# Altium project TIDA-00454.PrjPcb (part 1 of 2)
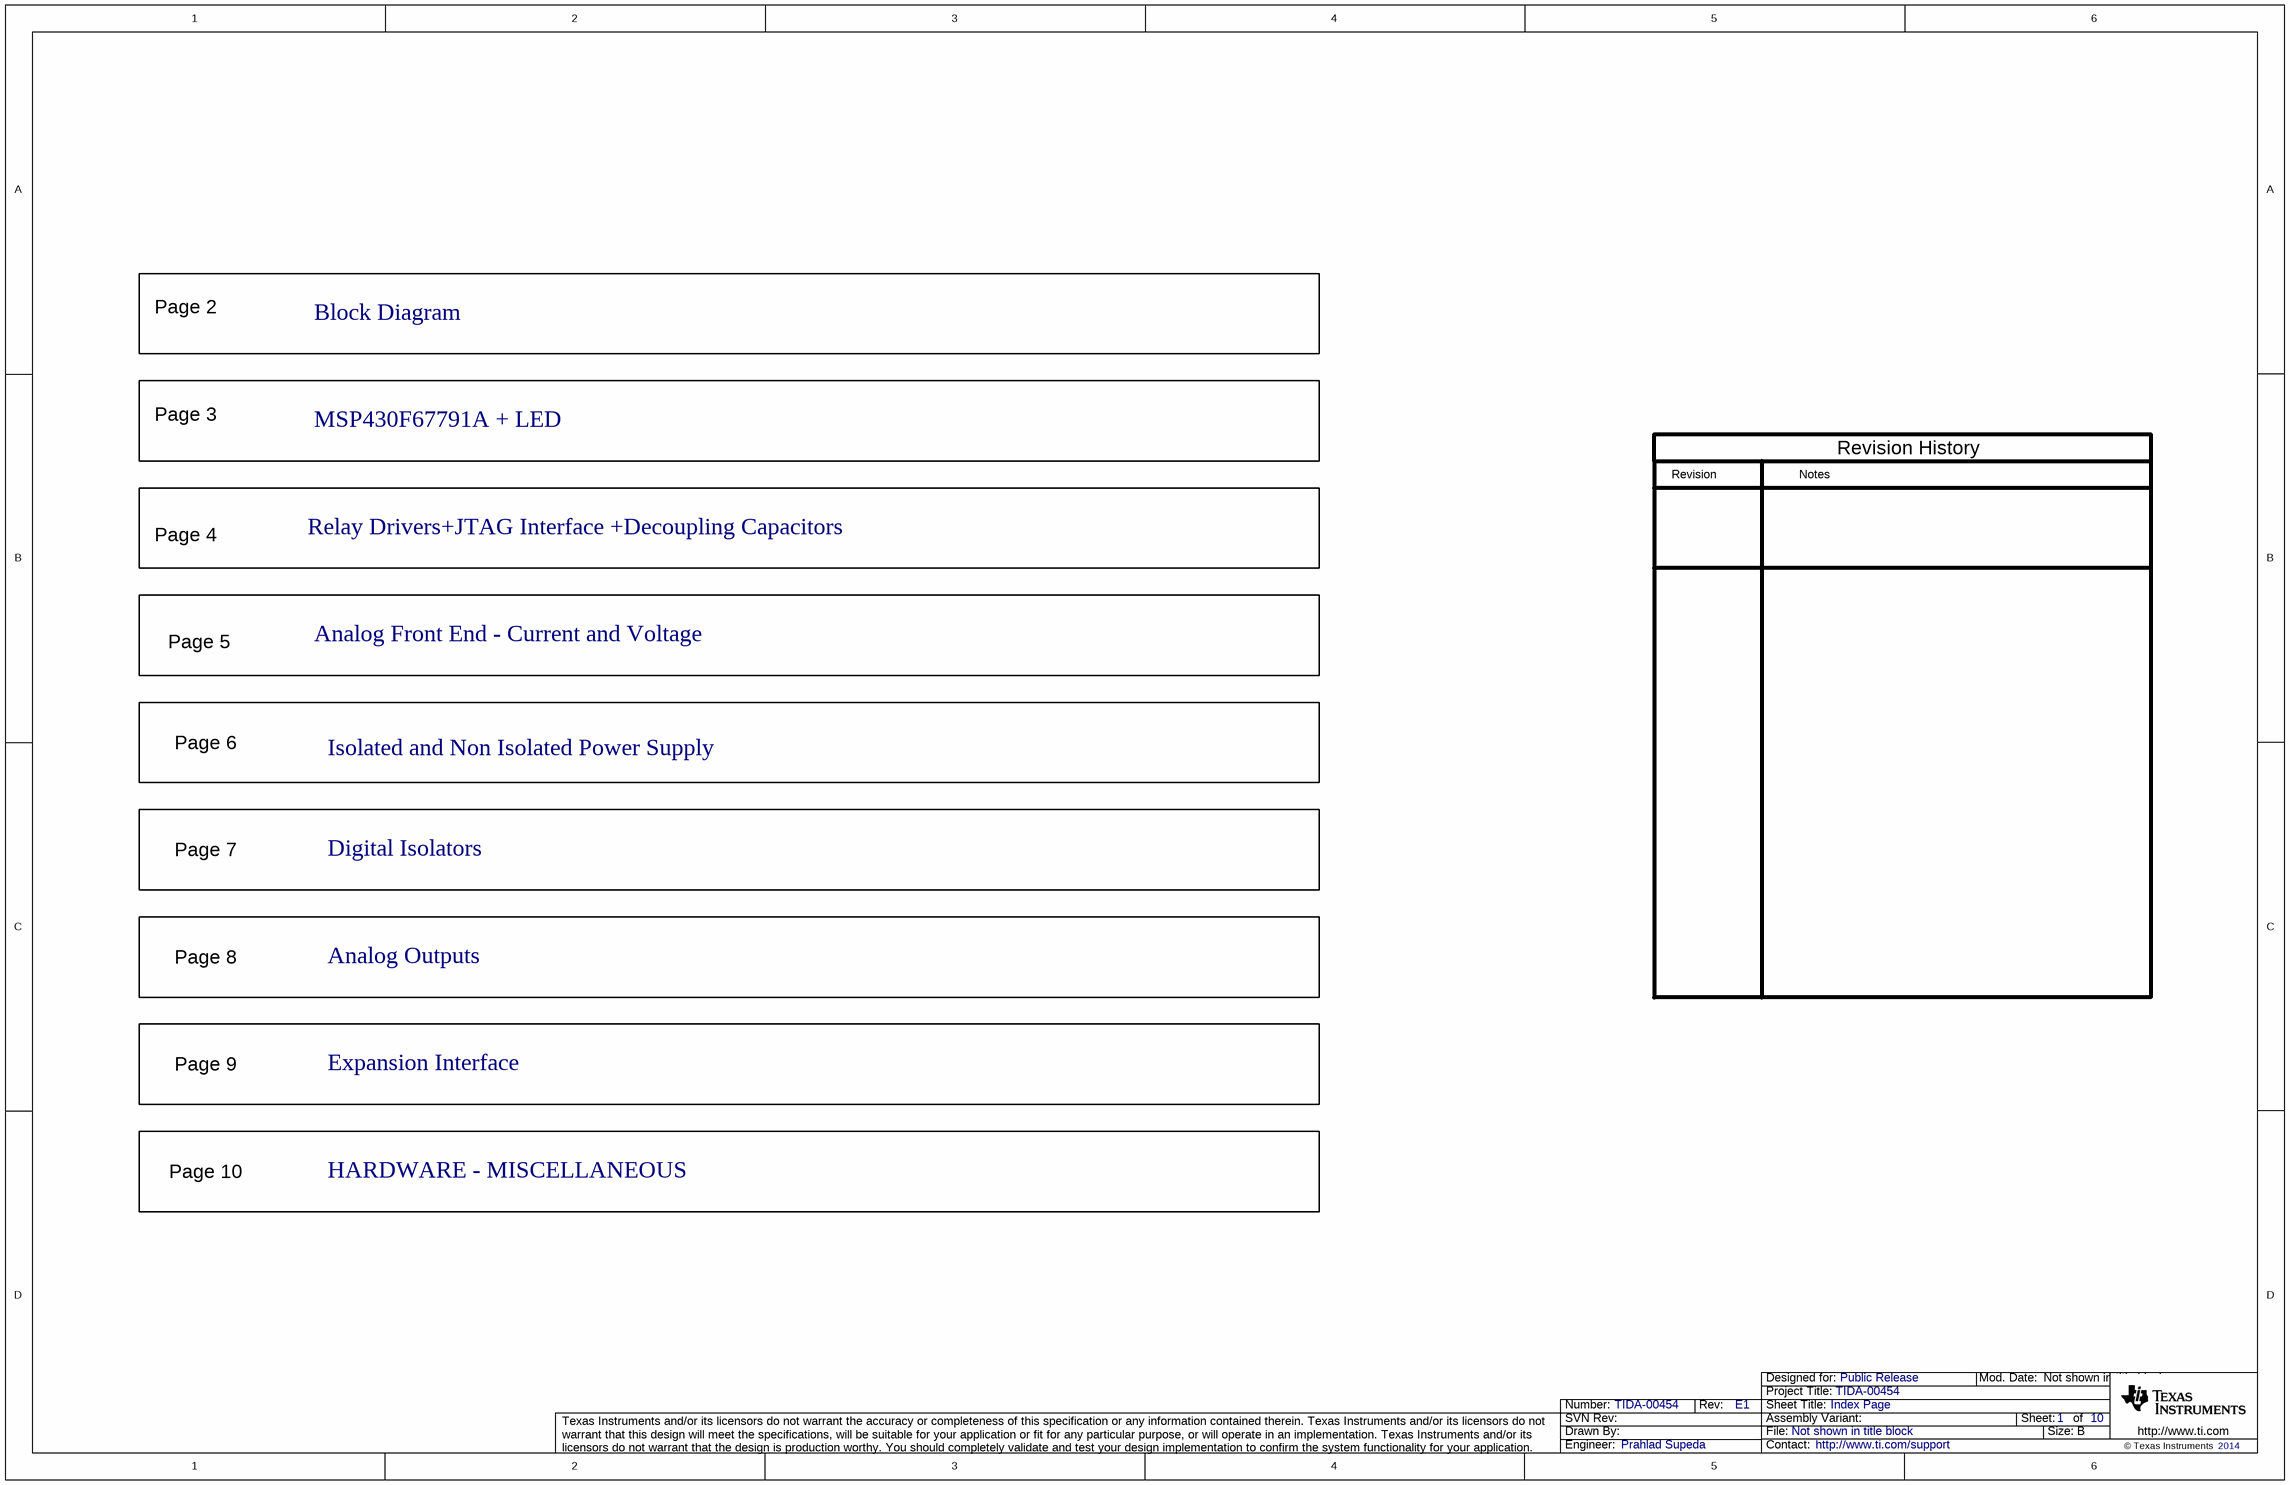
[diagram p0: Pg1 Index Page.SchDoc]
CopyrightYear: 2014; PCB_Rev: E1; PRJ_Customer: Public Release; PRJ_Engineer: Prahlad Supeda; PRJ_Number: TIDA-00454; PRJ_Title: TIDA-00454; SCH_Rev: E1; TechSupport: http://www.ti.com/support
10 sheets, 327 parts. Net scope: flat (ports and power ports of the same name join across sheets).
Board file: TIDA-00454.PcbDoc
Sheets:
  Pg1 Index Page.SchDoc
  Pg2 Block Diagram.SchDoc
  Pg3.MSP430F67791A+LED.SchDoc
  Pg4. Relay Drivers+JTAG Interface +Decoupling Capacitors.SchDoc
  Pg5.Analog Front End - Current and Voltage.SchDoc
  Pg6.Isolated and Non Isolated Power Supply.SchDoc
  Pg7.Digital Isolators.SchDoc
  Pg8. Analog Outputs.SchDoc
  Pg9 Expansion Interface.SchDoc
  Pg10.HARDWARE - MISCELLANEOUS..SchDoc

## Sheet Pg1 Index Page.SchDoc: Index Page
size 431 x 279 mm; Date: Not shown in title block; ApprovedBy: Not shown in title block; CheckedBy: Not shown in title block; Author: Not shown in title block; CompanyName: Not shown in title block; Engineer: Not shown in title block; Organization: Not shown in title block; Address1: Not shown in title block; Address2: Not shown in title block; Address3: Not shown in title block; Address4: Not shown in title block; DocumentNumber: 1; Revision: Use project parameter SCH_Rev; SheetNumber: 1; SheetTotal: 10; PageSetup: Record=PageOptions¦CenterHorizontal=True¦CenterVertical=True¦PrintScale=1.00¦XCorrection=1.00¦YCorrection=1.00¦PrintKind=0¦BorderSize=5000000¦LeftOffset=0¦BottomOffset=0¦Orientation=2¦PaperLength=1000¦PaperWidth=1000¦Scale=100¦PaperSource=15¦PrintQuality=600¦MediaType=1¦DitherType=10¦PaperKind=Letter¦PrintScaleMode=1

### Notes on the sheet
- Page 2
- Block Diagram
- Page 3
- MSP430F67791A + LED
- Revision
- Notes
- Revision History
- Page 4
- Relay Drivers+JTAG Interface +Decoupling Capacitors
- Page 5
- Analog Front End - Current and Voltage
- Page 6
- Isolated and Non Isolated Power Supply
- Page 7
- Digital Isolators
- Page 8
- Analog Outputs
- Page 9
- Expansion Interface
- Page 10
- HARDWARE - MISCELLANEOUS

## Sheet Pg2 Block Diagram.SchDoc: Block Diagram
size 431 x 279 mm; Date: Not shown in title block; ApprovedBy: Not shown in title block; CheckedBy: Not shown in title block; Author: Not shown in title block; CompanyName: Not shown in title block; Engineer: Not shown in title block; Organization: Not shown in title block; Address1: Not shown in title block; Address2: Not shown in title block; Address3: Not shown in title block; Address4: Not shown in title block; DocumentNumber: 2; Revision: Use project parameter SCH_Rev; SheetNumber: 2; SheetTotal: 10; PageSetup: Record=PageOptions|CenterHorizontal=True|CenterVertical=True|PrintScale=1.00|XCorrection=1.00|YCorrection=1.00|PrintKind=0|BorderSize=5000000|LeftOffset=0|BottomOffset=0|Orientation=2|PaperLength=1000|PaperWidth=1000|Scale=100|PaperSource=15|PrintQuality=600|MediaType=1|DitherType=10|PaperKind=Letter|PrintScaleMode=1

## Sheet Pg3.MSP430F67791A+LED.SchDoc: MSP430F6779 + Crystal
size 431 x 279 mm; Date: Not shown in title block; ApprovedBy: Not shown in title block; CheckedBy: Not shown in title block; Author: Not shown in title block; CompanyName: Not shown in title block; Engineer: Not shown in title block; Organization: Not shown in title block; Address1: Not shown in title block; Address2: Not shown in title block; Address3: Not shown in title block; Address4: Not shown in title block; DocumentNumber: 6; Revision: Use project parameter SCH_Rev; SheetNumber: 3; SheetTotal: 10; PageSetup: Record=PageOptions¦CenterHorizontal=True¦CenterVertical=True¦PrintScale=1.00¦XCorrection=1.00¦YCorrection=1.00¦PrintKind=0¦BorderSize=5000000¦LeftOffset=0¦BottomOffset=0¦Orientation=2¦PaperLength=1000¦PaperWidth=1000¦Scale=100¦PaperSource=15¦PrintQuality=600¦MediaType=1¦DitherType=10¦PaperKind=Letter¦PrintScaleMode=1
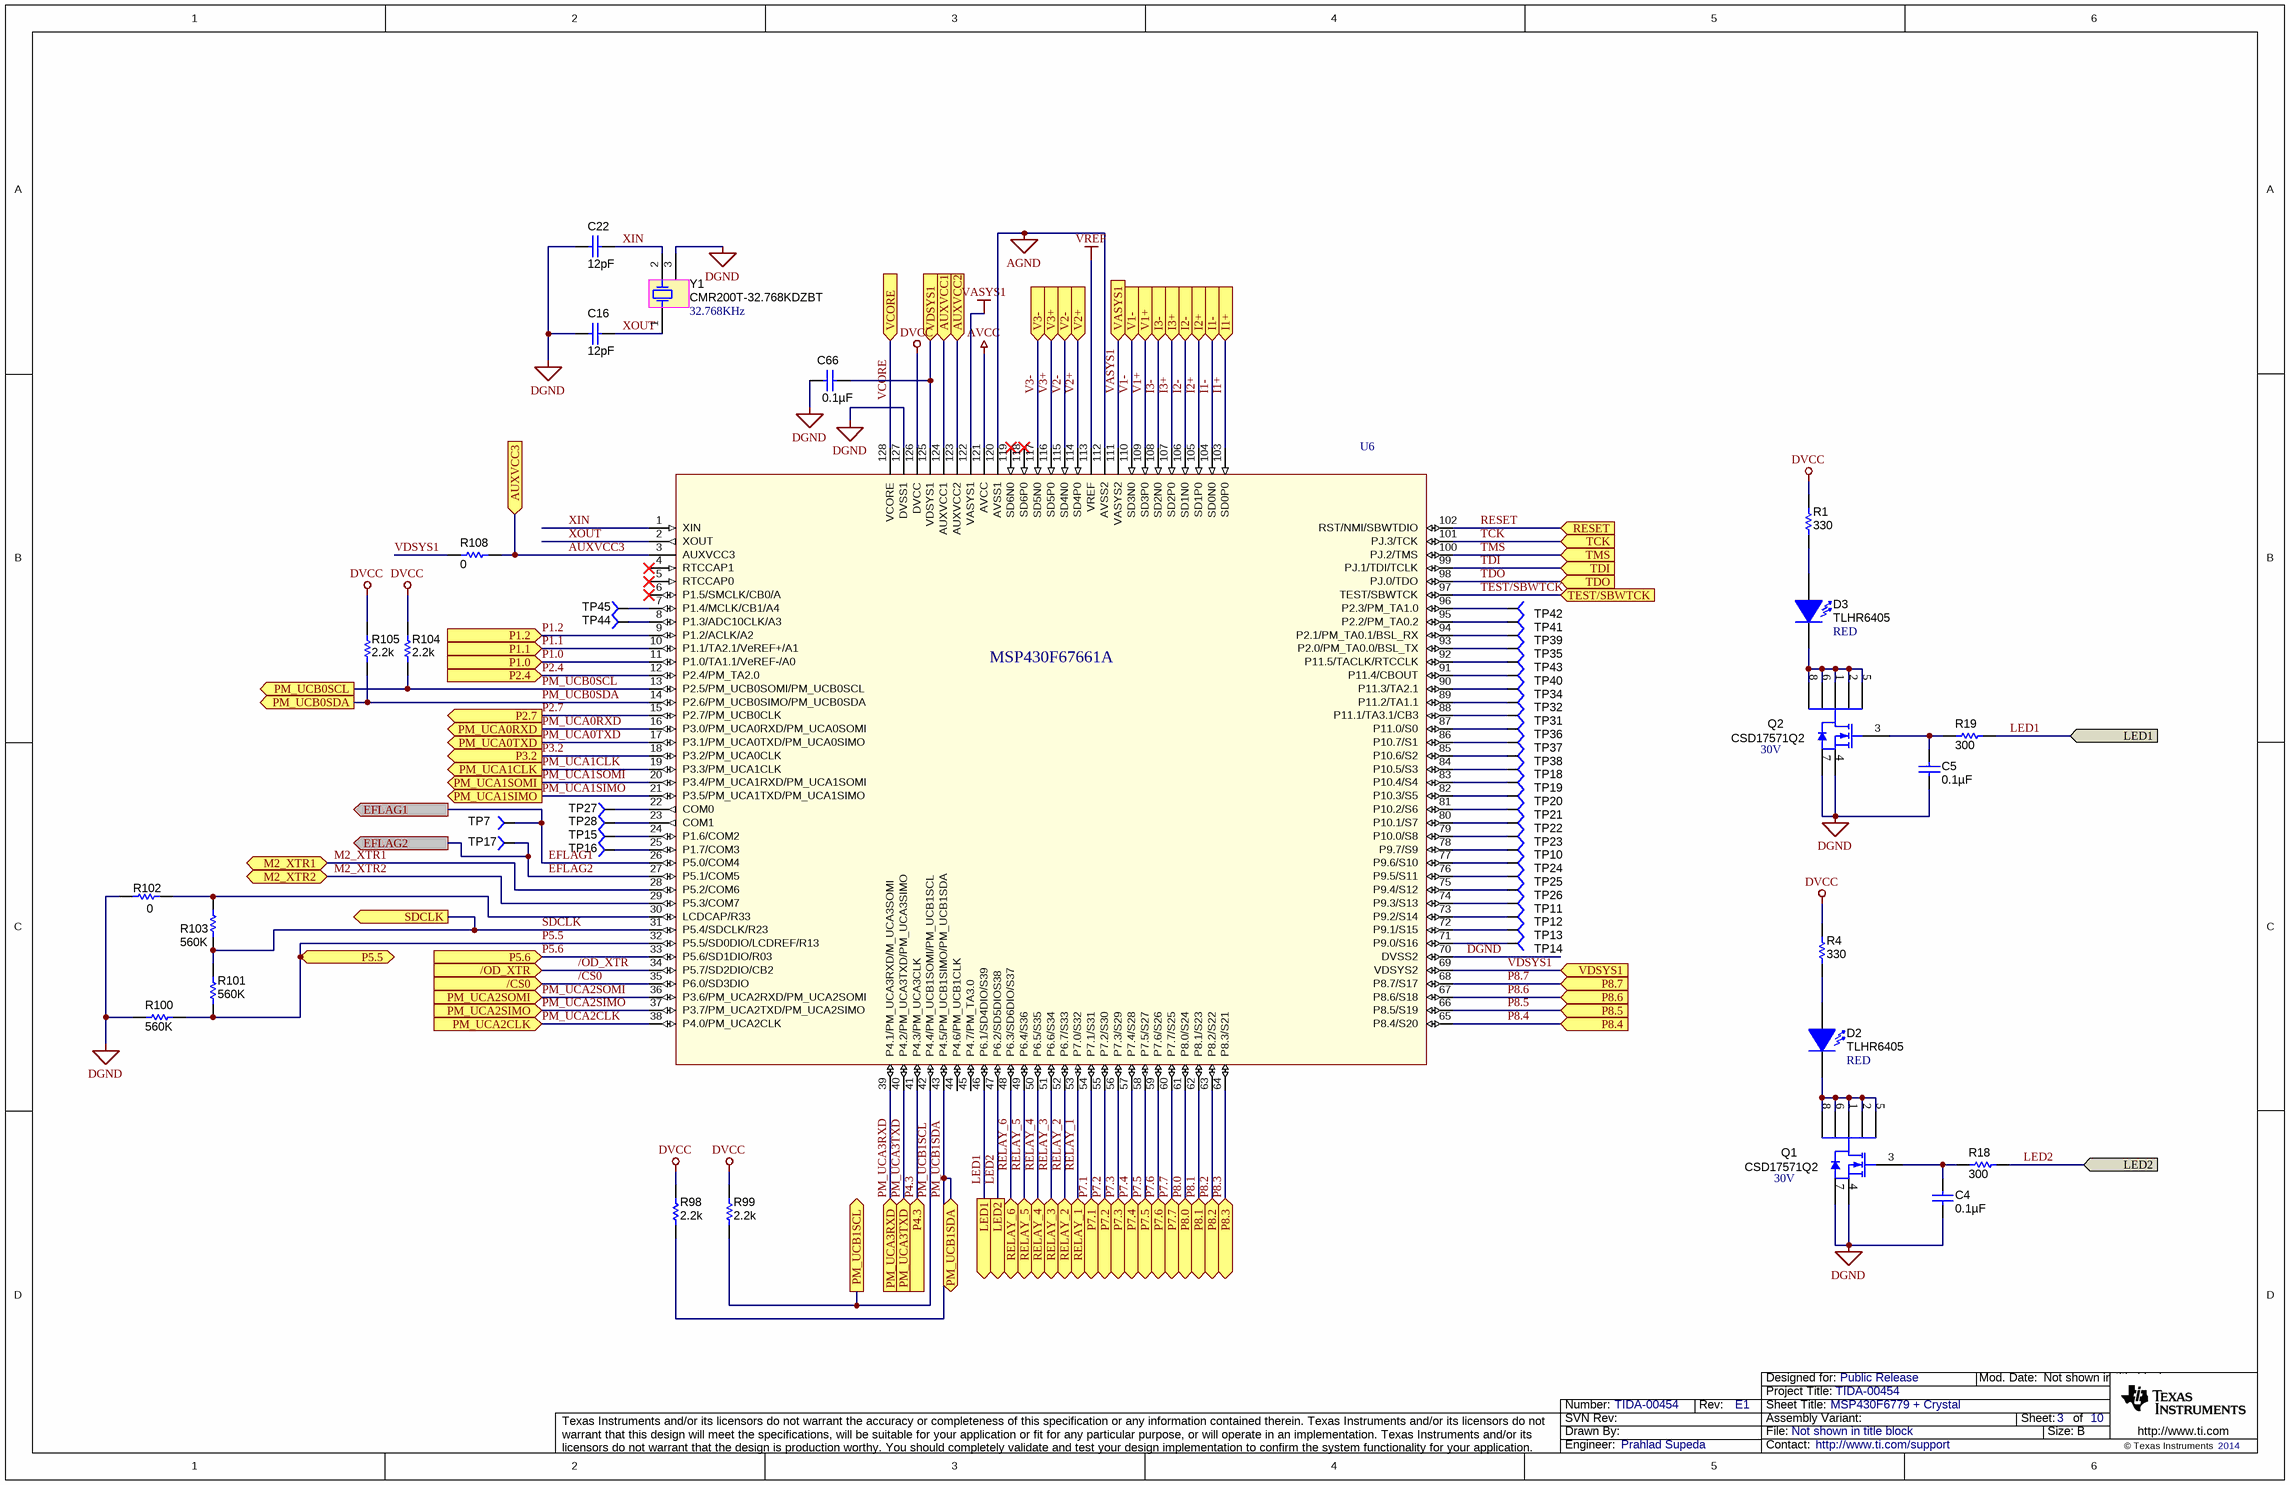
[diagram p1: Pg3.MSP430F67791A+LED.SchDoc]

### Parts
C4  ValueDisplayed: 0.1µF  [0603]  (hidden comment: 06033C104JAT2A)
C5  ValueDisplayed: 0.1µF  [0603]  (hidden comment: 06033C104JAT2A)
C16  ValueDisplayed: 12pF  [0603]  (hidden comment: 06035A120JAT2A)
C22  ValueDisplayed: 12pF  [0603]  (hidden comment: 06035A120JAT2A)
C66  ValueDisplayed: 0.1µF  [0603]  (hidden comment: 06033C104JAT2A)
D2  TLHR6405  value RED  [LED_5MM]
D3  TLHR6405  value RED  [LED_5MM]
Q1  CSD17571Q2  value 30V  [SON_CSD17571Q2]
Q2  CSD17571Q2  value 30V  [SON_CSD17571Q2]
R1  value 330  [0603]  (hidden comment: CRCW0603330RJNEA)
R4  value 330  [0603]  (hidden comment: CRCW0603330RJNEA)
R18  value 300  [0603]  (hidden comment: CRCW0603300RJNEA)
R19  value 300  [0603]  (hidden comment: CRCW0603300RJNEA)
R98  value 2.2k  [0603]  (hidden comment: CRCW06032K20JNEA)
R99  value 2.2k  [0603]  (hidden comment: CRCW06032K20JNEA)
R100  value 560K  [0603]  (hidden comment: CRCW0603560KFKEA)
R101  value 560K  [0603]  (hidden comment: CRCW0603560KFKEA)
R102  value 0  [0603]  (hidden comment: CRCW06030000Z0EA)
R103  value 560K  [0603]  (hidden comment: CRCW0603560KFKEA)
R104  value 2.2k  [0603]  (hidden comment: CRCW06032K20JNEA)
R105  value 2.2k  [0603]  (hidden comment: CRCW06032K20JNEA)
R108  value 0  [0805_HV]  (hidden comment: CRCW08050000Z0EA)
TP7  TP-040_RND  [TP_25MIL-SMT]  (value not drawn)
TP10  TP-040_RND  [TP_25MIL-SMT]  (value not drawn)
TP11  TP-040_RND  [TP_25MIL-SMT]  (value not drawn)
TP12  TP-040_RND  [TP_25MIL-SMT]  (value not drawn)
TP13  TP-040_RND  [TP_25MIL-SMT]  (value not drawn)
TP14  TP-040_RND  [TP_25MIL-SMT]  (value not drawn)
TP15  TP-040_RND  [TP_25MIL-SMT]  (value not drawn)
TP16  TP-040_RND  [TP_25MIL-SMT]  (value not drawn)
TP17  TP-040_RND  [TP_25MIL-SMT]  (value not drawn)
TP18  TP-040_RND  [TP_25MIL-SMT]  (value not drawn)
TP19  TP-040_RND  [TP_25MIL-SMT]  (value not drawn)
TP20  TP-040_RND  [TP_25MIL-SMT]  (value not drawn)
TP21  TP-040_RND  [TP_25MIL-SMT]  (value not drawn)
TP22  TP-040_RND  [TP_25MIL-SMT]  (value not drawn)
TP23  TP-040_RND  [TP_25MIL-SMT]  (value not drawn)
TP24  TP-040_RND  [TP_25MIL-SMT]  (value not drawn)
TP25  TP-040_RND  [TP_25MIL-SMT]  (value not drawn)
TP26  TP-040_RND  [TP_25MIL-SMT]  (value not drawn)
TP27  TP-040_RND  [TP_25MIL-SMT]  (value not drawn)
TP28  TP-040_RND  [TP_25MIL-SMT]  (value not drawn)
TP31  TP-040_RND  [TP_25MIL-SMT]  (value not drawn)
TP32  TP-040_RND  [TP_25MIL-SMT]  (value not drawn)
TP34  TP-040_RND  [TP_25MIL-SMT]  (value not drawn)
TP35  TP-040_RND  [TP_25MIL-SMT]  (value not drawn)
TP36  TP-040_RND  [TP_25MIL-SMT]  (value not drawn)
TP37  TP-040_RND  [TP_25MIL-SMT]  (value not drawn)
TP38  TP-040_RND  [TP_25MIL-SMT]  (value not drawn)
TP39  TP-040_RND  [TP_25MIL-SMT]  (value not drawn)
TP40  TP-040_RND  [TP_25MIL-SMT]  (value not drawn)
TP41  TP-040_RND  [TP_25MIL-SMT]  (value not drawn)
TP42  TP-040_RND  [TP_25MIL-SMT]  (value not drawn)
TP43  TP-040_RND  [TP_25MIL-SMT]  (value not drawn)
TP44  TP-040_RND  [TP_25MIL-SMT]  (value not drawn)
TP45  TP-040_RND  [TP_25MIL-SMT]  (value not drawn)
U6  MSP430F67661A  [QFP50P1600X2200X160-128N]
Y1  CMR200T-32.768KDZBT  Frequency: 32.768KHz  [XTAL_CMR200T]

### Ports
/CS0 (in), /OD_XTR (in), AUXVCC1 (in), AUXVCC2 (in), AUXVCC3 (in), EFLAG1 (out), EFLAG2 (out), I1+ (in), I1- (in), I2+ (in), I2- (in), I3+ (in), I3- (in), LED1 (in), LED1 (out), LED2 (in), LED2 (out), M2_XTR1, M2_XTR2, P1.0 (in), P1.1 (in), P1.2 (in), P2.4 (in), P2.7 (out), P3.2 (out), P4.3 (in), P5.5 (in), P5.6 (in), P7.1, P7.2, P7.3, P7.4, P7.5, P7.6, P7.7, P8.0, P8.1, P8.2, P8.3, P8.4 (in), P8.5 (in), P8.6 (in), P8.7 (in), PM_UCA0RXD (out), PM_UCA0TXD (out), PM_UCA1CLK (out), PM_UCA1SIMO (out), PM_UCA1SOMI (out), PM_UCA2CLK (in), PM_UCA2SIMO (in), PM_UCA2SOMI (in), PM_UCA3RXD (in), PM_UCA3TXD (in), PM_UCB0SCL (out), PM_UCB0SDA (out), PM_UCB1SCL (out), PM_UCB1SDA (bidir), RELAY_1, RELAY_2, RELAY_3, RELAY_4, RELAY_5, RELAY_6, RESET (in), SDCLK (out), TCK (in), TDI (in), TDO (in), TEST/SBWTCK (in), TMS (in), V1+ (in), V1- (in), V2+ (in), V2- (in), V3+ (in), V3- (in), VASYS1 (in), VCORE (in), VDSYS1 (in)

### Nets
AGND: U6.112(AVSS2) U6.120(AVSS1)
AVCC: U6.121(AVCC)
DGND: C4.2 C5.2 C16.2 C22.2 C66.1 Q1.4(S) Q1.7(S) Q2.4(S) Q2.7(S) R100.2 R102.1 U6.70(DVSS2) U6.127(DVSS1) Y1.3
DVCC: R1.2 R4.2 R98.2 R99.2 R104.2 R105.2 U6.126(DVCC)
VASYS1: U6.111(VASYS2) U6.122(VASYS1) ; port VASYS1
VREF: U6.113(VREF)
/CS0: U6.35(P6.0/SD3DIO) ; port /CS0
/OD_XTR: U6.34(P5.7/SD2DIO/CB2) ; port /OD_XTR
AUXVCC1: U6.124(AUXVCC1) ; port AUXVCC1
AUXVCC2: U6.123(AUXVCC2) ; port AUXVCC2
AUXVCC3: R108.2 U6.3(AUXVCC3) ; port AUXVCC3
EFLAG1: TP7.1 U6.26(P5.0/COM4) ; port EFLAG1
EFLAG2: TP17.1 U6.27(P5.1/COM5) ; port EFLAG2
I1+: U6.103(SD0P0) ; port I1+
I1-: U6.104(SD0N0) ; port I1-
I2+: U6.105(SD1P0) ; port I2+
I2-: U6.106(SD1N0) ; port I2-
I3+: U6.107(SD2P0) ; port I3+
I3-: U6.108(SD2N0) ; port I3-
LED1: R19.1 U6.46(P6.1/SD4DIO/S39) ; port LED1
LED2: R18.1 U6.47(P6.2/SD5DIOS38) ; port LED2
M2_XTR1: U6.28(P5.2/COM6) ; port M2_XTR1
M2_XTR2: U6.29(P5.3/COM7) ; port M2_XTR2
P1.0: U6.11(P1.0/TA1.1/VeREF-/A0) ; port P1.0
P1.1: U6.10(P1.1/TA2.1/VeREF+/A1) ; port P1.1
P1.2: U6.9(P1.2/ACLK/A2) ; port P1.2
P2.4: U6.12(P2.4/PM_TA2.0) ; port P2.4
P2.7: U6.15(P2.7/PM_UCB0CLK) ; port P2.7
P3.2: U6.18(P3.2/PM_UCA0CLK) ; port P3.2
P4.3: U6.41(P4.3/PM_UCA3CLK) ; port P4.3
P5.5: R100.1 R101.1 U6.32(P5.5/SD0DIO/LCDREF/R13) ; port P5.5
P5.6: U6.33(P5.6/SD1DIO/R03) ; port P5.6
P7.1: U6.54(P7.1/S31) ; port P7.1
P7.2: U6.55(P7.2/S30) ; port P7.2
P7.3: U6.56(P7.3/S29) ; port P7.3
P7.4: U6.57(P7.4/S28) ; port P7.4
P7.5: U6.58(P7.5/S27) ; port P7.5
P7.6: U6.59(P7.6/S26) ; port P7.6
P7.7: U6.60(P7.7/S25) ; port P7.7
P8.0: U6.61(P8.0/S24) ; port P8.0
P8.1: U6.62(P8.1/S23) ; port P8.1
P8.2: U6.63(P8.2/S22) ; port P8.2
P8.3: U6.64(P8.3/S21) ; port P8.3
P8.4: U6.65(P8.4/S20) ; port P8.4
P8.5: U6.66(P8.5/S19) ; port P8.5
P8.6: U6.67(P8.6/S18) ; port P8.6
P8.7: U6.68(P8.7/S17) ; port P8.7
PM_UCA0RXD: U6.16(P3.0/PM_UCA0RXD/PM_UCA0SOMI) ; port PM_UCA0RXD
PM_UCA0TXD: U6.17(P3.1/PM_UCA0TXD/PM_UCA0SIMO) ; port PM_UCA0TXD
PM_UCA1CLK: U6.19(P3.3/PM_UCA1CLK) ; port PM_UCA1CLK
PM_UCA1SIMO: U6.21(P3.5/PM_UCA1TXD/PM_UCA1SIMO) ; port PM_UCA1SIMO
PM_UCA1SOMI: U6.20(P3.4/PM_UCA1RXD/PM_UCA1SOMI) ; port PM_UCA1SOMI
PM_UCA2CLK: U6.38(P4.0/PM_UCA2CLK) ; port PM_UCA2CLK
PM_UCA2SIMO: U6.37(P3.7/PM_UCA2TXD/PM_UCA2SIMO) ; port PM_UCA2SIMO
PM_UCA2SOMI: U6.36(P3.6/PM_UCA2RXD/PM_UCA2SOMI) ; port PM_UCA2SOMI
PM_UCA3RXD: U6.39(P4.1/PM_UCA3RXD/M_UCA3SOMI) ; port PM_UCA3RXD
PM_UCA3TXD: U6.40(P4.2/PM_UCA3TXD/PM_UCA3SIMO) ; port PM_UCA3TXD
PM_UCB0SCL: R104.1 U6.13(P2.5/PM_UCB0SOMI/PM_UCB0SCL) ; port PM_UCB0SCL
PM_UCB0SDA: R105.1 U6.14(P2.6/PM_UCB0SIMO/PM_UCB0SDA) ; port PM_UCB0SDA
PM_UCB1SCL: R99.1 U6.42(P4.4/PM_UCB1SOMI/PM_UCB1SCL) ; port PM_UCB1SCL
PM_UCB1SDA: R98.1 U6.43(P4.5/PM_UCB1SIMO/PM_UCB1SDA) ; port PM_UCB1SDA
RELAY_1: U6.53(P7.0/S32) ; port RELAY_1
RELAY_2: U6.52(P6.7/S33) ; port RELAY_2
RELAY_3: U6.51(P6.6/S34) ; port RELAY_3
RELAY_4: U6.50(P6.5/S35) ; port RELAY_4
RELAY_5: U6.49(P6.4/S36) ; port RELAY_5
RELAY_6: U6.48(P6.3/SD6DIO/S37) ; port RELAY_6
RESET: U6.102(RST/NMI/SBWTDIO) ; port RESET
SDCLK: R101.2 R103.1 U6.31(P5.4/SDCLK/R23) ; port SDCLK
TCK: U6.101(PJ.3/TCK) ; port TCK
TDI: U6.99(PJ.1/TDI/TCLK) ; port TDI
TDO: U6.98(PJ.0/TDO) ; port TDO
TEST/SBWTCK: U6.97(TEST/SBWTCK) ; port TEST/SBWTCK
TMS: U6.100(PJ.2/TMS) ; port TMS
V1+: U6.109(SD3P0) ; port V1+
V1-: U6.110(SD3N0) ; port V1-
V2+: U6.114(SD4P0) ; port V2+
V2-: U6.115(SD4N0) ; port V2-
V3+: U6.116(SD5P0) ; port V3+
V3-: U6.117(SD5N0) ; port V3-
VCORE: U6.128(VCORE) ; port VCORE
VDSYS1: C66.2 R108.1 U6.69(VDSYS2) U6.125(VDSYS1) ; port VDSYS1
XIN: C22.1 U6.1(XIN) Y1.2
XOUT: C16.1 U6.2(XOUT) Y1.1
NetC4_1: C4.1 Q1.3(G) R18.2
NetC5_1: C5.1 Q2.3(G) R19.2
NetD2_1: D2.1(K) Q1.1(D) Q1.2(D) Q1.5(D) Q1.6(D) Q1.8(D)
NetD2_2: D2.2(A) R4.1
NetD3_1: D3.1(K) Q2.1(D) Q2.2(D) Q2.5(D) Q2.6(D) Q2.8(D)
NetD3_2: D3.2(A) R1.1
NetR102_2: R102.2 R103.2 U6.30(LCDCAP/R33)
NetTP10_1: TP10.1 U6.78(P9.7/S9)
NetTP11_1: TP11.1 U6.74(P9.3/S13)
NetTP12_1: TP12.1 U6.73(P9.2/S14)
NetTP13_1: TP13.1 U6.72(P9.1/S15)
NetTP14_1: TP14.1 U6.71(P9.0/S16)
NetTP15_1: TP15.1 U6.24(P1.6/COM2)
NetTP16_1: TP16.1 U6.25(P1.7/COM3)
NetTP18_1: TP18.1 U6.84(P10.5/S3)
NetTP19_1: TP19.1 U6.83(P10.4/S4)
NetTP20_1: TP20.1 U6.82(P10.3/S5)
NetTP21_1: TP21.1 U6.81(P10.2/S6)
NetTP22_1: TP22.1 U6.80(P10.1/S7)
NetTP23_1: TP23.1 U6.79(P10.0/S8)
NetTP24_1: TP24.1 U6.77(P9.6/S10)
NetTP25_1: TP25.1 U6.76(P9.5/S11)
NetTP26_1: TP26.1 U6.75(P9.4/S12)
NetTP27_1: TP27.1 U6.22(COM0)
NetTP28_1: TP28.1 U6.23(COM1)
NetTP31_1: TP31.1 U6.88(P11.1/TA3.1/CB3)
NetTP32_1: TP32.1 U6.89(P11.2/TA1.1)
NetTP34_1: TP34.1 U6.90(P11.3/TA2.1)
NetTP35_1: TP35.1 U6.93(P2.0/PM_TA0.0/BSL_TX)
NetTP36_1: TP36.1 U6.87(P11.0/S0)
NetTP37_1: TP37.1 U6.86(P10.7/S1)
NetTP38_1: TP38.1 U6.85(P10.6/S2)
NetTP39_1: TP39.1 U6.94(P2.1/PM_TA0.1/BSL_RX)
NetTP40_1: TP40.1 U6.91(P11.4/CBOUT)
NetTP41_1: TP41.1 U6.95(P2.2/PM_TA0.2)
NetTP42_1: TP42.1 U6.96(P2.3/PM_TA1.0)
NetTP43_1: TP43.1 U6.92(P11.5/TACLK/RTCCLK)
NetTP44_1: TP44.1 U6.8(P1.3/ADC10CLK/A3)
NetTP45_1: TP45.1 U6.7(P1.4/MCLK/CB1/A4)

Not connected (* = marked no-connect by the designer): U6 4(RTCCAP1)* 5(RTCCAP0)* 6(P1.5/SMCLK/CB0/A)* 44(P4.6/PM_UCB1CLK) 45(P4.7/PM_TA3.0) 118(SD6P0)* 119(SD6N0)*

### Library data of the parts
C4 C5 C66 = 06033C104JAT2A: CAP, CERM, 0.1uF, 25V, +/-5%, X7R, 0603; Manufacturer: AVX; Polarized: N; CompType: Capacitor; U/M: EA; Cap_F: 0.0000001; Tolerance_%: 5; ESR_Ohm: 0.05; Value1: 0.05 ohm; VDC_V: 25; TaMin_C: -55; TaMax_C: 125
C16 C22 = 06035A120JAT2A: CAP, CERM, 12pF, 50V, +/-5%, C0G/NP0, 0603; Manufacturer: AVX; Polarized: N; CompType: Capacitor; U/M: EA; Cap_F: 0.000000000012; Tolerance_%: 5; ESR_Ohm: 0.363; Value1: 0.363 ohm; VDC_V: 50; TaMin_C: -55; TaMax_C: 125
D2 D3 = TLHR6405: LED, 5MM, RED, TH; Manufacturer: VISHAY; SymbolCreator: x0199378
Q1 Q2 = CSD17571Q2: MOSFET, N-CH, 30V, 22A, SON 2X2 MM; Manufacturer: TEXAS INSTRUMENTS; CompType: POWER MOSFET
R1 R4 = CRCW0603330RJNEA: RES, 330 ohm, 5%, 0.1W, 0603; Manufacturer: Vishay-Dale; CompType: Resistor; Value_Code: 330R; Tolerance_%: 5; Power_W: 0.1; VDC_V: 75; TempCo: 200 ppm/C; EIA_Code: E24; U/M: EA
R18 R19 = CRCW0603300RJNEA: RES, 300 ohm, 5%, 0.1W, 0603; Manufacturer: Vishay-Dale; CompType: Resistor; Value_Code: 300R; Tolerance_%: 5; Power_W: 0.1; VDC_V: 75; TempCo: 200 ppm/C; EIA_Code: E24; U/M: EA
R98 R99 R104 R105 = CRCW06032K20JNEA: RES, 2.2k ohm, 5%, 0.1W, 0603; Manufacturer: Vishay-Dale; CompType: Resistor; Res_ohm: 2200; Value_Code: 2k20; Tolerance_%: 5; Power_W: 0.1; VDC_V: 75; TempCo: 200 ppm/C; EIA_Code: E24; U/M: EA
R100 R101 R103 = CRCW06032K20JNEA: RES 560K OHM 1/10W 1% 0603 SMD; Manufacturer: Vishay-Dale; CompType: Resistor; Tolerance_%: 1; Power_W: 0.1; Value2: 0.1W; VDC_V: 75; TempCo: 100 ppm/C; EIA_Code: E24; U/M: EA
R102 = CRCW08050000Z0EA: RES 0.0 OHM 1/10W JUMP 0603 SMD; Manufacturer: Vishay-Dale; CompType: Resistor; Value_Code: 0000; Tolerance_%: 5; Power_W: 0.125; Value2: 0.1W; VDC_V: 150; EIA_Code: E24; U/M: EA
R108 = CRCW0805330KJNEA: RES, 0 ohm, 5%, 0.125W, 0805; Manufacturer: Vishay-Dale; CompType: Resistor; Tolerance_%: 5; Power_W: 0.125; VDC_V: 150; TempCo: 200 ppm/C; EIA_Code: E24; U/M: EA
TP7 TP10-TP28 TP35-TP38 TP44 TP45 = TP-040_RND: Test Point, SMT 25mil; Manufacturer: STD; Value: STD
TP31 TP32 TP34 TP39-TP43 = TP-040_RND: Test Point, O.040 Hole; Manufacturer: STD; Value: STD
U6 = MSP430F6779IPEU: IC, MCU 16BIT 512KB FLASH, LQFP-128; Manufacturer: TEXAS INSTRUMENTS; SymbolCreator: x0199378
Y1 = CMR200T-32.768KDZBT: CRYSTAL, 32.768KHz, 6PF, +/- 20PPM, SMD-3P; Manufacturer: CITIZEN; SymbolCreator: x0199378

## Sheet Pg4. Relay Drivers+JTAG Interface +Decoupling Capacitors.SchDoc: JTAG Interface + LEDs + Decoupling Capacitors
size 431 x 279 mm; Date: Not shown in title block; ApprovedBy: Not shown in title block; CheckedBy: Not shown in title block; Author: Not shown in title block; CompanyName: Not shown in title block; Engineer: Not shown in title block; Organization: Not shown in title block; Address1: Not shown in title block; Address2: Not shown in title block; Address3: Not shown in title block; Address4: Not shown in title block; DocumentNumber: 5; Revision: Use project parameter SCH_Rev; SheetNumber: 4; SheetTotal: 10; PageSetup: Record=PageOptions¦CenterHorizontal=True¦CenterVertical=True¦PrintScale=1.00¦XCorrection=1.00¦YCorrection=1.00¦PrintKind=0¦BorderSize=5000000¦LeftOffset=0¦BottomOffset=0¦Orientation=2¦PaperLength=1000¦PaperWidth=1000¦Scale=100¦PaperSource=15¦PrintQuality=600¦MediaType=1¦DitherType=10¦PaperKind=Letter¦PrintScaleMode=1
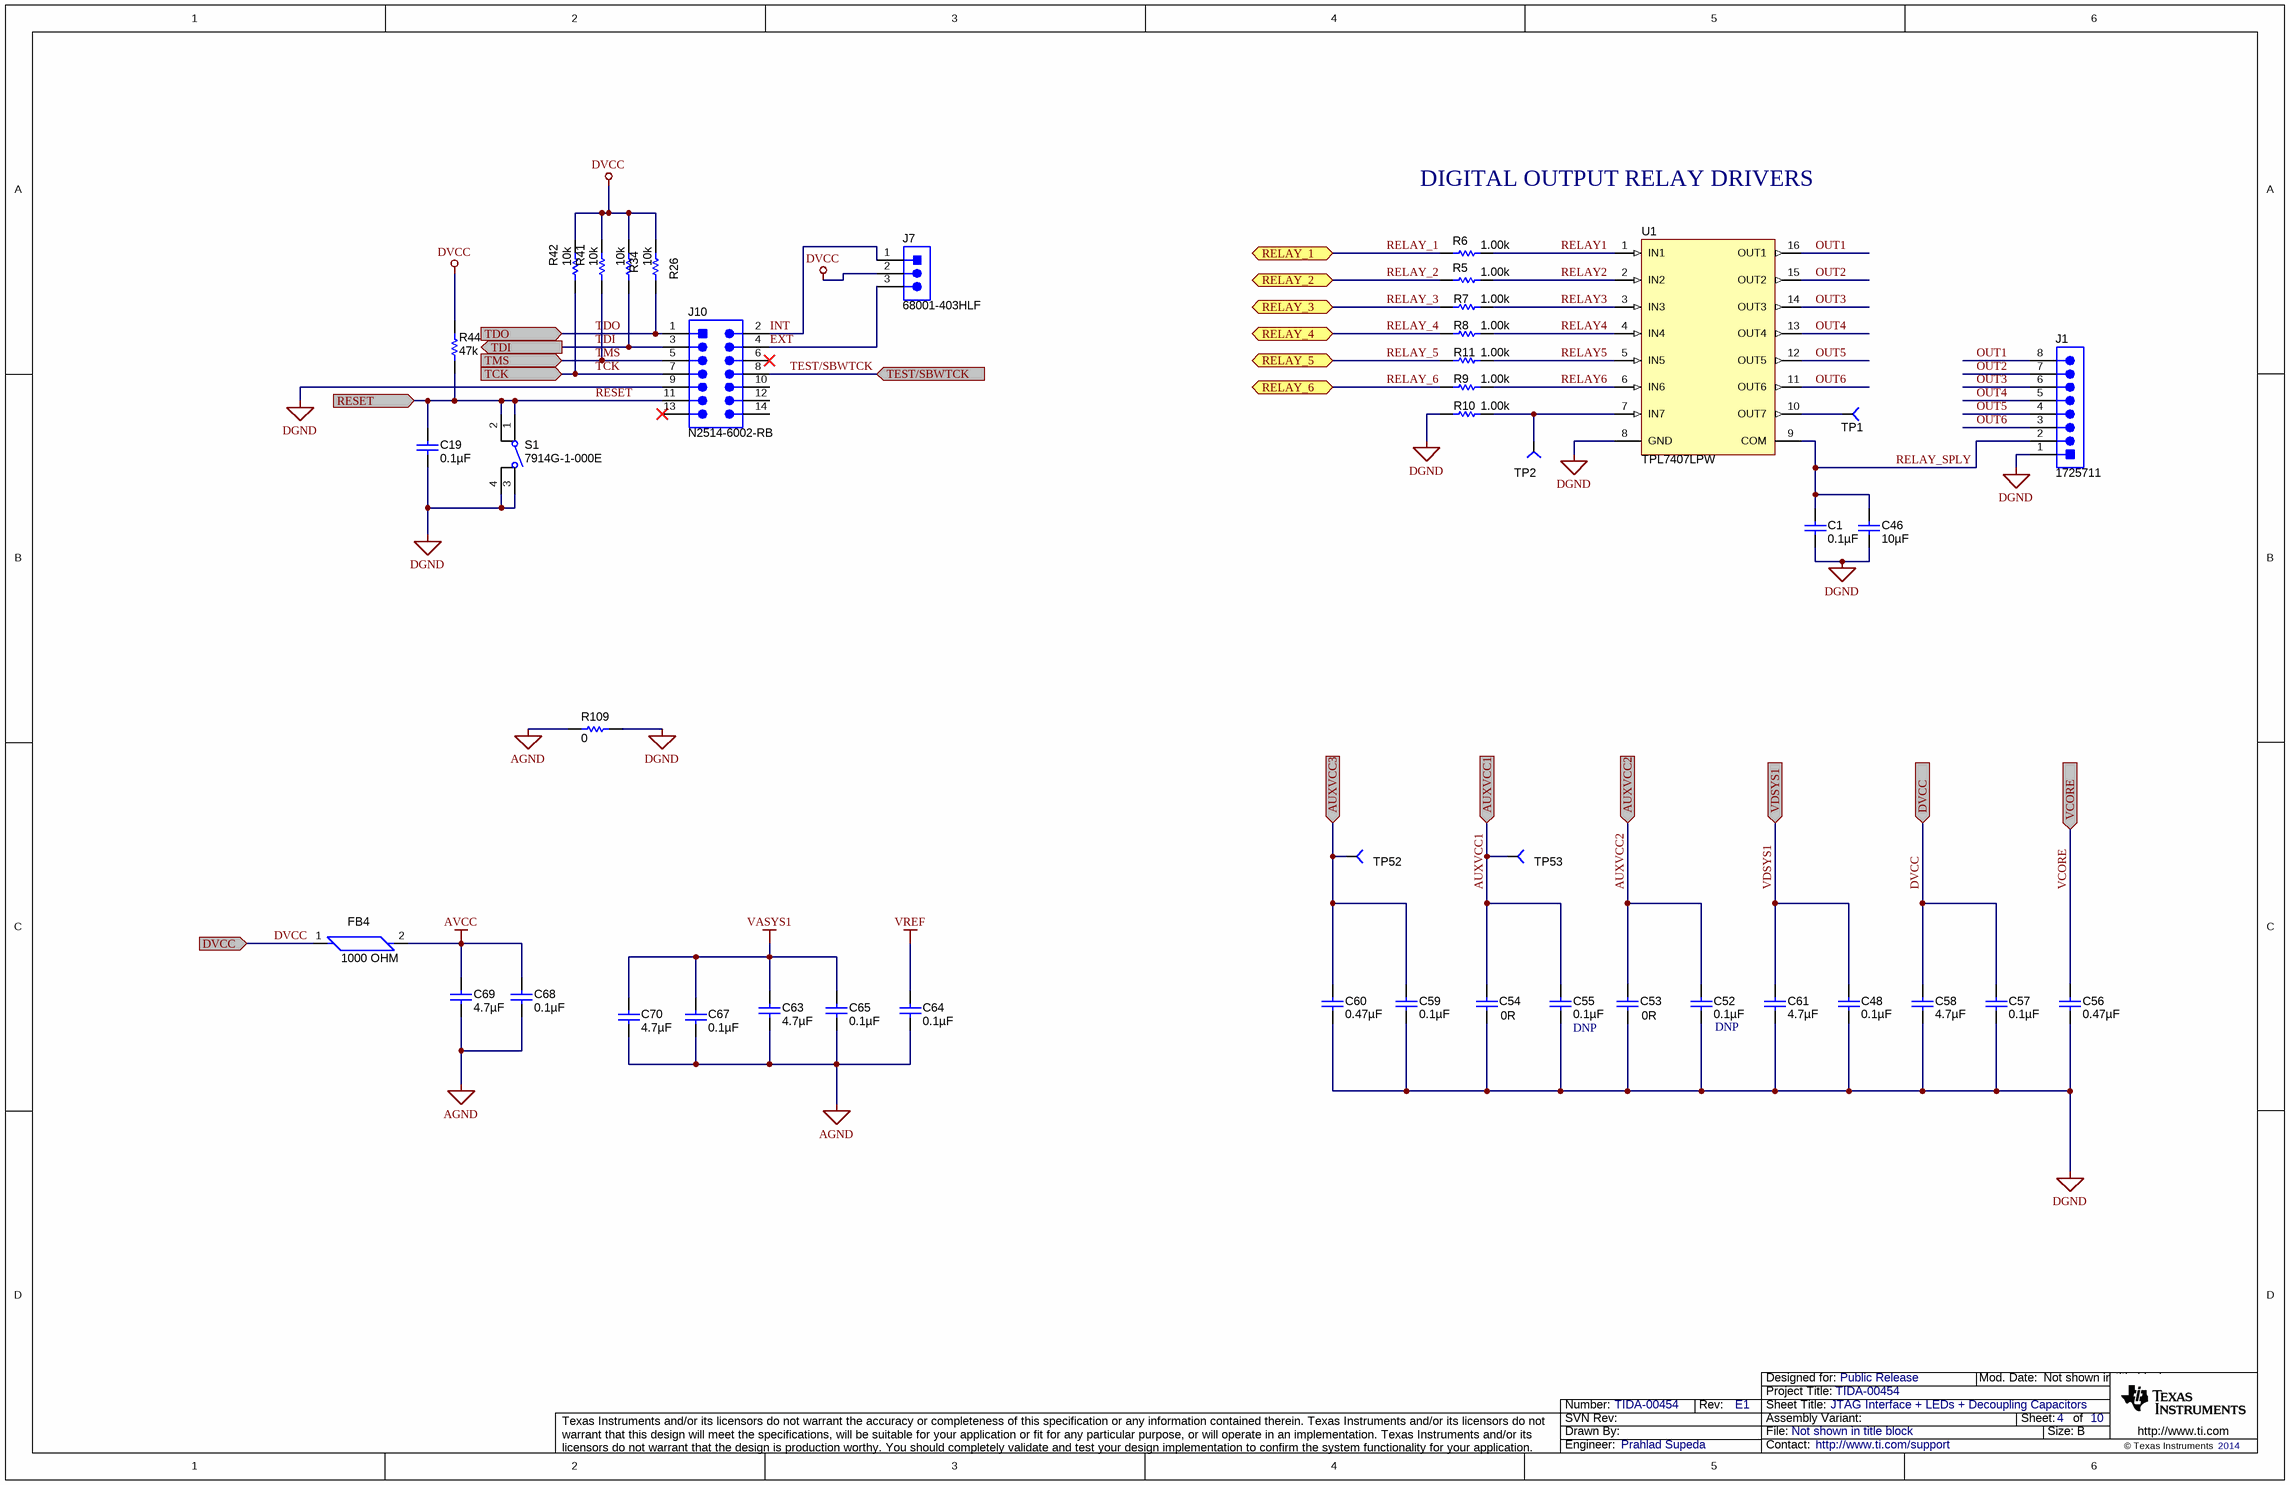
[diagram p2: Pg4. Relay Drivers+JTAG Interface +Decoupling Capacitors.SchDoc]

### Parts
C1  ValueDisplayed: 0.1µF  [0603]  (hidden comment: 06035C104KAT2A)
C19  ValueDisplayed: 0.1µF  [0603]  (hidden comment: 06033C104JAT2A)
C46  ValueDisplayed: 10µF  [1210]  (hidden comment: GRM32ER71H106KA12L)
C48  ValueDisplayed: 0.1µF  [0603]  (hidden comment: 06033C104JAT2A)
C52  ValueDisplayed: 0.1µF  Fitted: DNP  [0603]  (hidden comment: 06033C104JAT2A)
C53  value 0R  [0603]  (hidden comment: CRCW06030000Z0EA)
C54  value 0R  [0603]  (hidden comment: CRCW06030000Z0EA)
C55  ValueDisplayed: 0.1µF  Fitted: DNP  [0603]  (hidden comment: 06033C104JAT2A)
C56  ValueDisplayed: 0.47µF  [0603]  (hidden comment: GRM188R71E474KA12J)
C57  ValueDisplayed: 0.1µF  [0603]  (hidden comment: 06033C104JAT2A)
C58  ValueDisplayed: 4.7µF  [0603]  (hidden comment: 0603ZD475KAT2A)
C59  ValueDisplayed: 0.1µF  [0603]  (hidden comment: 06033C104JAT2A)
C60  ValueDisplayed: 0.47µF  [0603]  (hidden comment: GRM188R71E474KA12J)
C61  ValueDisplayed: 4.7µF  [0603]  (hidden comment: 0603ZD475KAT2A)
C63  ValueDisplayed: 4.7µF  [0603]  (hidden comment: 0603ZD475KAT2A)
C64  ValueDisplayed: 0.1µF  [0603]  (hidden comment: 06033C104JAT2A)
C65  ValueDisplayed: 0.1µF  [0603]  (hidden comment: 06033C104JAT2A)
C67  ValueDisplayed: 0.1µF  [0603]  (hidden comment: 06033C104JAT2A)
C68  ValueDisplayed: 0.1µF  [0603]  (hidden comment: 06033C104JAT2A)
C69  ValueDisplayed: 4.7µF  [0603]  (hidden comment: 0603ZD475KAT2A)
C70  ValueDisplayed: 4.7µF  [0603]  (hidden comment: 0603ZD475KAT2A)
FB4  1000 OHM  [0603]
J1  1725711  [CONN_1725711]
J7  68001-403HLF  [HDR1X3]
J10  N2514-6002-RB  [3M_N2514-6002-RB]
R5  value 1.00k  [0603]  (hidden comment: CRCW06031K00FKEA)
R6  value 1.00k  [0603]  (hidden comment: CRCW06031K00FKEA)
R7  value 1.00k  [0603]  (hidden comment: CRCW06031K00FKEA)
R8  value 1.00k  [0603]  (hidden comment: CRCW06031K00FKEA)
R9  value 1.00k  [0603]  (hidden comment: CRCW06031K00FKEA)
R10  value 1.00k  [0603]  (hidden comment: CRCW06031K00FKEA)
R11  value 1.00k  [0603]  (hidden comment: CRCW06031K00FKEA)
R26  value 10k  [0603]  (hidden comment: CRCW060310K0JNEA)
R34  value 10k  [0603]  (hidden comment: CRCW060310K0JNEA)
R41  value 10k  [0603]  (hidden comment: CRCW060310K0JNEA)
R42  value 10k  [0603]  (hidden comment: CRCW060310K0JNEA)
R44  value 47k  [0603]  (hidden comment: CRCW060347K0JNEA)
R109  value 0  [0805_HV]  (hidden comment: CRCW08050000Z0EA)
S1  7914G-1-000E  [SW_7914G-1-000E]
TP1  TP-038  [TP1_PD40_D0.5_S50]  (value not drawn)
TP2  TP-038  [TP1_PD40_D0.5_S50]  (value not drawn)
TP52  TP-040_RND  [TP_25MIL-SMT]  (value not drawn)
TP53  TP-040_RND  [TP_25MIL-SMT]  (value not drawn)
U1  TPL7407LPW  [PW0016A_N]

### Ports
AUXVCC1, AUXVCC2, AUXVCC3, DVCC, RELAY_1, RELAY_2, RELAY_3, RELAY_4, RELAY_5, RELAY_6, RESET, TCK, TDI (out), TDO, TEST/SBWTCK, TMS, VCORE, VDSYS1

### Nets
AGND: C63.2 C64.2 C65.2 C67.2 C68.2 C69.2 C70.2 R109.1
AVCC: C68.1 C69.1 FB4.2
DGND: C1.2 C19.1 C46.2 C48.2 C52.2 C53.2 C54.2 C55.2 C56.2 C57.2 C58.2 C59.2 C60.2 C61.2 J1.1 J10.9 R10.1 R109.2 S1.3 S1.4 U1.8(GND)
DVCC: C57.1 C58.1 FB4.1 J7.2 R26.1 R34.1 R41.1 R42.1 R44.2 ; port DVCC
VASYS1: C63.1 C65.1 C67.1 C70.1
VREF: C64.1
AUXVCC1: C54.1 C55.1 TP53.1 ; port AUXVCC1
AUXVCC2: C52.1 C53.1 ; port AUXVCC2
AUXVCC3: C59.1 C60.1 TP52.1 ; port AUXVCC3
EXT: J7.3 J10.4
INT: J7.1 J10.2
OUT1: J1.8 U1.16(OUT1)
OUT2: J1.7 U1.15(OUT2)
OUT3: J1.6 U1.14(OUT3)
OUT4: J1.5 U1.13(OUT4)
OUT5: J1.4 U1.12(OUT5)
OUT6: J1.3 U1.11(OUT6)
RELAY1: R6.2 U1.1(IN1)
RELAY2: R5.2 U1.2(IN2)
RELAY3: R7.2 U1.3(IN3)
RELAY4: R8.2 U1.4(IN4)
RELAY5: R11.2 U1.5(IN5)
RELAY6: R9.2 U1.6(IN6)
RELAY_1: R6.1 ; port RELAY_1
RELAY_2: R5.1 ; port RELAY_2
RELAY_3: R7.1 ; port RELAY_3
RELAY_4: R8.1 ; port RELAY_4
RELAY_5: R11.1 ; port RELAY_5
RELAY_6: R9.1 ; port RELAY_6
RELAY_SPLY: C1.1 C46.1 J1.2 U1.9(COM)
RESET: C19.2 J10.11 R44.1 S1.1 S1.2 ; port RESET
TCK: J10.7 R42.2 ; port TCK
TDI: J10.3 R34.2 ; port TDI
TDO: J10.1 R26.2 ; port TDO
TEST/SBWTCK: J10.8 ; port TEST/SBWTCK
TMS: J10.5 R41.2 ; port TMS
VCORE: C56.1 ; port VCORE
VDSYS1: C48.1 C61.1 ; port VDSYS1
NetR10_2: R10.2 TP2.1 U1.7(IN7)
NetTP1_1: TP1.1 U1.10(OUT7)

Not connected (* = marked no-connect by the designer): J10 6* 10 12 13* 14

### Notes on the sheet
- DIGITAL OUTPUT RELAY DRIVERS

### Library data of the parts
C1 = 06035C104KAT2A: CAP, CERM, 0.1uF, 50V, +/-10%, X7R, 0603; Manufacturer: AVX; Polarized: N; CompType: Capacitor; U/M: EA; Cap_F: 0.0000001; Tolerance_%: 10; Value1: Unknown; VDC_V: 50; TaMin_C: -55; TaMax_C: 125
C19 C48 C52 C55 C57 C59 C64 C65 C67 C68 = 06033C104JAT2A: as C4 on sheet Pg3.MSP430F67791A+LED
C46 = GRM32ER71H106KA12L: CAP, CERM, 10uF, 50V, +/-10%, X7R, 1210; Manufacturer: MuRata; Polarized: N; CompType: Capacitor; U/M: EA; Cap_F: 0.00001; Tolerance_%: 10; Value1: Unknown; VDC_V: 50; TaMin_C: -55; TaMax_C: 125
C53 C54 = 0603ZD475KAT2A: RES 0.0 OHM 1/10W JUMP 0603 SMD; Manufacturer: Vishay-Dale; CompType: Capacitor; U/M: EA; Cap_F: 0.0000047; Value1: Unknown; TaMin_C: -55; TaMax_C: 85
C56 C60 = GRM188R71E474KA12D: CAP, CERM, 0.47uF, 25V, +/-10%, X7R, 0603; Manufacturer: MuRata; Polarized: N; CompType: Capacitor; U/M: EA; Cap_F: 0.00000047; Tolerance_%: 10; Value1: Unknown; VDC_V: 25; TaMin_C: -55; TaMax_C: 125
C58 C61 C63 C69 C70 = 0603ZD475KAT2A: CAP, CERM, 4.7uF, 10V, +/-10%, X5R, 0603; Manufacturer: AVX; Polarized: N; CompType: Capacitor; U/M: EA; Cap_F: 0.0000047; Tolerance_%: 10; Value1: Unknown; TaMin_C: -55; TaMax_C: 85
FB4 = MMZ1608B102C: FERRITE CHIP 1000 OHM 300MA 0603; Manufacturer: TDK Corporation; CompType: Ferrite Bead
J1 = 1725711: Terminal Block, 8x1, 2.54 mm, TH; Manufacturer: Phoenix Contact; SymbolCreator: a0411947; U/M: EA
J7 = 009155003301006: 3 pin berger; Manufacturer: FCI; SymbolCreator: a0799628; CompType: Connector; U/M: EA
J10 = 0015912140: Header, 7x2, 100mil, SMT; Manufacturer: Molex; SymbolCreator: a0412235; U/M: EA
R5-R11 = CRCW06031K00FKEA: RES, 1.00k ohm, 1%, 0.1W, 0603; Manufacturer: Vishay-Dale; CompType: Resistor; Res_ohm: 1000; Value_Code: 1k00; Tolerance_%: 1; Power_W: 0.1; VDC_V: 75; TempCo: 100 ppm/C; EIA_Code: E96; U/M: EA
R26 R34 R41 R42 = RNCF0603TKY10K0: RES 10K OHM 1/10W 5% 0603 SMD; Manufacturer: Vishay-Dale; CompType: Resistor; Res_ohm: 10000; Value_Code: 10k0; Tolerance_%: 0.01; Value1: 0.01%; Power_W: 0.063; Value2: 0.063W; VDC_V: 50; TempCo: 5 ppm/C; U/M: EA
R44 = CRCW060347K0JNEA: RES, 47k ohm, 5%, 0.1W, 0603; Manufacturer: Vishay-Dale; CompType: Resistor; Res_ohm: 47000; Value_Code: 47k0; Tolerance_%: 5; Power_W: 0.1; VDC_V: 75; TempCo: 200 ppm/C; EIA_Code: E24; U/M: EA
R109 = CRCW0805330KJNEA: as R108 on sheet Pg3.MSP430F67791A+LED
S1 = 7914G-1-000E: Switch, Tactile, SPST-NO, 0.1A, 16V, SMT; Manufacturer: Bourns; SymbolCreator: a0412235; VDC_V: 16; SwitchFunction: Off-Mom; PositionCount: 1; CurrentRating_mA: 100
TP1 TP2 = TP-038: Test Point 40mil pad 20mil drill; Manufacturer: STD; Value: STD
TP52 TP53 = TP-040_RND: as TP31 on sheet Pg3.MSP430F67791A+LED
U1 = TPL7407LPW: 40V 7-Channel Low Side Driver, PW0016A; Alternate Manufacturer: None; Manufacturer: Texas Instruments; SymbolCreator: a0411947; CompType: IC; U/M: EA

## Sheet Pg5.Analog Front End - Current and Voltage.SchDoc: Analog Front End (Current)
size 431 x 279 mm; Date: Not shown in title block; ApprovedBy: Not shown in title block; CheckedBy: Not shown in title block; Author: Not shown in title block; CompanyName: Not shown in title block; Engineer: Not shown in title block; Organization: Not shown in title block; Address1: Not shown in title block; Address2: Not shown in title block; Address3: Not shown in title block; Address4: Not shown in title block; DocumentNumber: 3; Revision: Use project parameter SCH_Rev; SheetNumber: 5; SheetTotal: 10; PageSetup: Record=PageOptions¦CenterHorizontal=True¦CenterVertical=True¦PrintScale=1.00¦XCorrection=1.00¦YCorrection=1.00¦PrintKind=0¦BorderSize=5000000¦LeftOffset=0¦BottomOffset=0¦Orientation=2¦PaperLength=1000¦PaperWidth=1000¦Scale=100¦PaperSource=15¦PrintQuality=600¦MediaType=1¦DitherType=10¦PaperKind=Letter¦PrintScaleMode=1
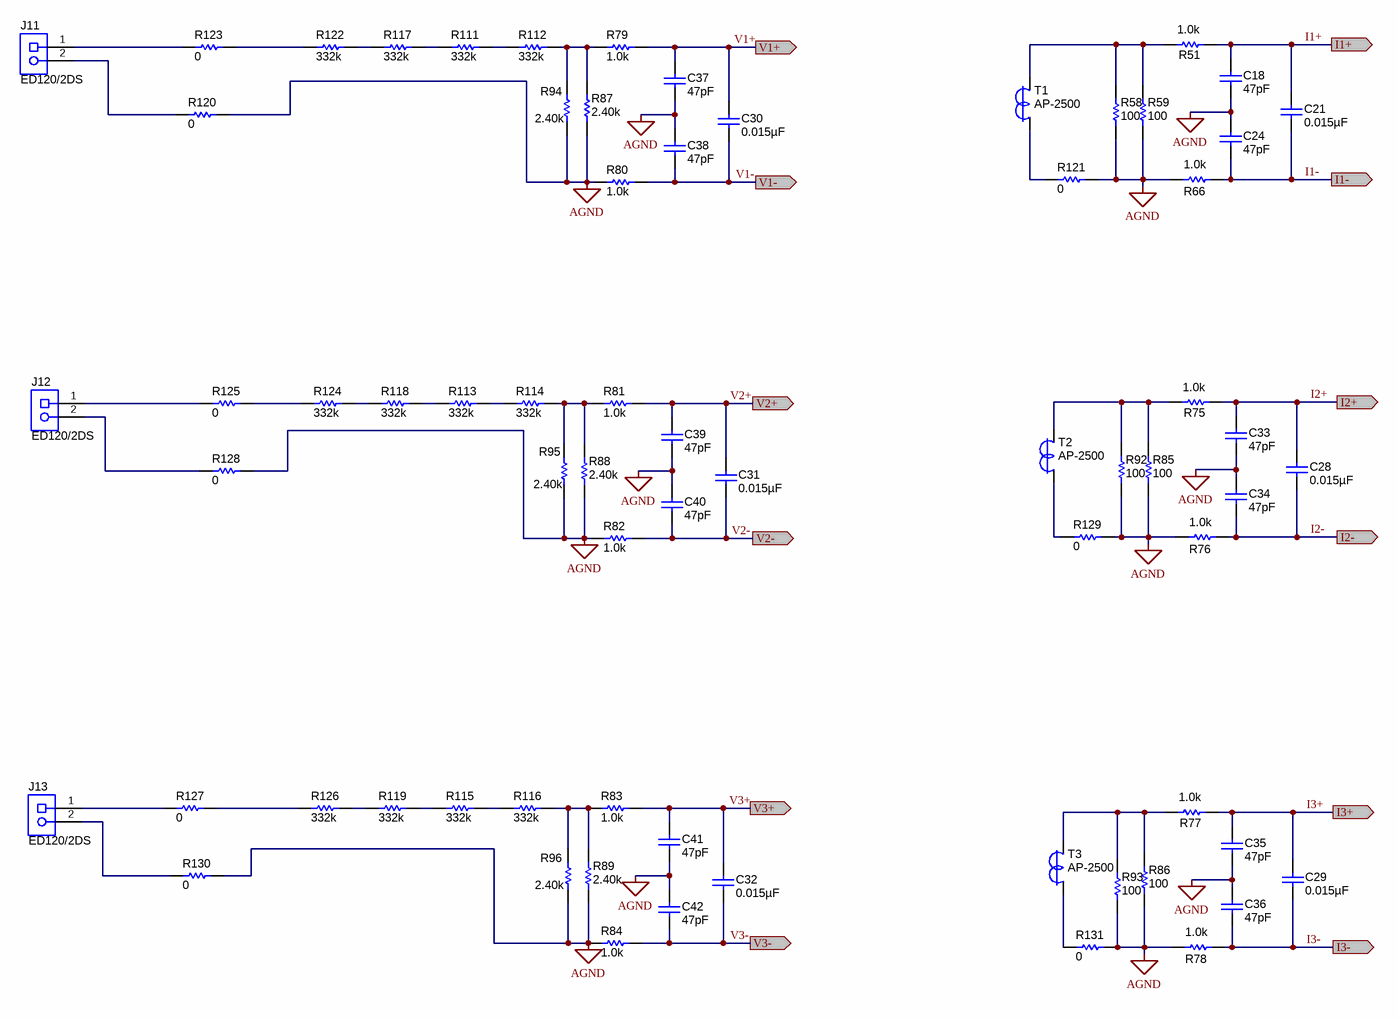
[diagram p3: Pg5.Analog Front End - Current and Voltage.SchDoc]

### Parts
C18  ValueDisplayed: 47pF  [0805_HV]  (hidden comment: GRM21A5C2E470JW01D)
C21  ValueDisplayed: 0.015µF  [0805_HV]  (hidden comment: 08055C153KAT2A)
C24  ValueDisplayed: 47pF  [0805_HV]  (hidden comment: GRM21A5C2E470JW01D)
C28  ValueDisplayed: 0.015µF  [0805_HV]  (hidden comment: 08055C153KAT2A)
C29  ValueDisplayed: 0.015µF  [0805_HV]  (hidden comment: 08055C153KAT2A)
C30  ValueDisplayed: 0.015µF  [0805_HV]  (hidden comment: 08055C153KAT2A)
C31  ValueDisplayed: 0.015µF  [0805_HV]  (hidden comment: 08055C153KAT2A)
C32  ValueDisplayed: 0.015µF  [0805_HV]  (hidden comment: 08055C153KAT2A)
C33  ValueDisplayed: 47pF  [0805_HV]  (hidden comment: GRM21A5C2E470JW01D)
C34  ValueDisplayed: 47pF  [0805_HV]  (hidden comment: GRM21A5C2E470JW01D)
C35  ValueDisplayed: 47pF  [0805_HV]  (hidden comment: GRM21A5C2E470JW01D)
C36  ValueDisplayed: 47pF  [0805_HV]  (hidden comment: GRM21A5C2E470JW01D)
C37  ValueDisplayed: 47pF  [0805_HV]  (hidden comment: GRM21A5C2E470JW01D)
C38  ValueDisplayed: 47pF  [0805_HV]  (hidden comment: GRM21A5C2E470JW01D)
C39  ValueDisplayed: 47pF  [0805_HV]  (hidden comment: GRM21A5C2E470JW01D)
C40  ValueDisplayed: 47pF  [0805_HV]  (hidden comment: GRM21A5C2E470JW01D)
C41  ValueDisplayed: 47pF  [0805_HV]  (hidden comment: GRM21A5C2E470JW01D)
C42  ValueDisplayed: 47pF  [0805_HV]  (hidden comment: GRM21A5C2E470JW01D)
J11  ED120/2DS  [CONN_ED120-2DS]
J12  ED120/2DS  [CONN_ED120-2DS]
J13  ED120/2DS  [CONN_ED120-2DS]
R51  value 1.0k  [0603]  (hidden comment: CRCW06031K00JNEA)
R58  value 100  [0603]  (hidden comment: CRCW0603100RFKEA)
R59  value 100  [0603]  (hidden comment: CRCW0603100RFKEA)
R66  value 1.0k  [0603]  (hidden comment: CRCW06031K00JNEA)
R75  value 1.0k  [0603]  (hidden comment: CRCW06031K00JNEA)
R76  value 1.0k  [0603]  (hidden comment: CRCW06031K00JNEA)
R77  value 1.0k  [0603]  (hidden comment: CRCW06031K00JNEA)
R78  value 1.0k  [0603]  (hidden comment: CRCW06031K00JNEA)
R79  value 1.0k  [0603]  (hidden comment: CRCW06031K00JNEA)
R80  value 1.0k  [0603]  (hidden comment: CRCW06031K00JNEA)
R81  value 1.0k  [0603]  (hidden comment: CRCW06031K00JNEA)
R82  value 1.0k  [0603]  (hidden comment: CRCW06031K00JNEA)
R83  value 1.0k  [0603]  (hidden comment: CRCW06031K00JNEA)
R84  value 1.0k  [0603]  (hidden comment: CRCW06031K00JNEA)
R85  value 100  [0603]  (hidden comment: CRCW0603100RFKEA)
R86  value 100  [0603]  (hidden comment: CRCW0603100RFKEA)
R87  ValueDisplayed: 2.40k  [1206]  (hidden comment: RC1206FR-072K4L)
R88  ValueDisplayed: 2.40k  [1206]  (hidden comment: RC1206FR-072K4L)
R89  ValueDisplayed: 2.40k  [1206]  (hidden comment: RC1206FR-072K4L)
R92  value 100  [0603]  (hidden comment: CRCW0603100RFKEA)
R93  value 100  [0603]  (hidden comment: CRCW0603100RFKEA)
R94  ValueDisplayed: 2.40k  [1206]  (hidden comment: RC1206FR-072K4L)
R95  ValueDisplayed: 2.40k  [1206]  (hidden comment: RC1206FR-072K4L)
R96  ValueDisplayed: 2.40k  [1206]  (hidden comment: RC1206FR-072K4L)
R111  ValueDisplayed: 332k  [1206]  (hidden comment: ERJ-8ENF3323V)
R112  ValueDisplayed: 332k  [1206]  (hidden comment: ERJ-8ENF3323V)
R113  ValueDisplayed: 332k  [1206]  (hidden comment: ERJ-8ENF3323V)
R114  ValueDisplayed: 332k  [1206]  (hidden comment: ERJ-8ENF3323V)
R115  ValueDisplayed: 332k  [1206]  (hidden comment: ERJ-8ENF3323V)
R116  ValueDisplayed: 332k  [1206]  (hidden comment: ERJ-8ENF3323V)
R117  ValueDisplayed: 332k  [1206]  (hidden comment: ERJ-8ENF3323V)
R118  ValueDisplayed: 332k  [1206]  (hidden comment: ERJ-8ENF3323V)
R119  ValueDisplayed: 332k  [1206]  (hidden comment: ERJ-8ENF3323V)
R120  ValueDisplayed: 0  [1206]  (hidden comment: CRCW12060000Z0EA)
R121  value 0  [0805_HV]  (hidden comment: CRCW08050000Z0EA)
R122  ValueDisplayed: 332k  [1206]  (hidden comment: ERJ-8ENF3323V)
R123  value 0  [0805_HV]  (hidden comment: CRCW08050000Z0EA)
R124  ValueDisplayed: 332k  [1206]  (hidden comment: ERJ-8ENF3323V)
R125  value 0  [0805_HV]  (hidden comment: CRCW08050000Z0EA)
R126  ValueDisplayed: 332k  [1206]  (hidden comment: ERJ-8ENF3323V)
R127  value 0  [0805_HV]  (hidden comment: CRCW08050000Z0EA)
R128  ValueDisplayed: 0  [1206]  (hidden comment: CRCW12060000Z0EA)
R129  value 0  [0805_HV]  (hidden comment: CRCW08050000Z0EA)
R130  ValueDisplayed: 0  [1206]  (hidden comment: CRCW12060000Z0EA)
R131  value 0  [0805_HV]  (hidden comment: CRCW08050000Z0EA)
T1  AP-2500  [XFMR_AP-2500]
T2  AP-2500  [XFMR_AP-2500]
T3  AP-2500  [XFMR_AP-2500]

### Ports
I1+ (out), I1- (out), I2+ (out), I2- (out), I3+ (out), I3- (out), V1+ (out), V1- (out), V2+ (out), V2- (out), V3+ (out), V3- (out)

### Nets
AGND: C18.2 C24.1 C33.2 C34.1 C35.2 C36.1 C37.2 C38.1 C39.2 C40.1 C41.2 C42.1 R58.1 R59.1 R66.2 R76.2 R78.2 R80.2 R82.2 R84.2 R85.1 R86.1 R87.2 R88.2 R89.2 R92.1 R93.1 R94.2 R95.2 R96.2 R120.2 R121.2 R128.2 R129.2 R130.2 R131.2
I1+: C18.1 C21.1 R51.1 ; port I1+
I1-: C21.2 C24.2 R66.1 ; port I1-
I2+: C28.1 C33.1 R75.1 ; port I2+
I2-: C28.2 C34.2 R76.1 ; port I2-
I3+: C29.1 C35.1 R77.1 ; port I3+
I3-: C29.2 C36.2 R78.1 ; port I3-
V1+: C30.1 C37.1 R79.1 ; port V1+
V1-: C30.2 C38.2 R80.1 ; port V1-
V2+: C31.1 C39.1 R81.1 ; port V2+
V2-: C31.2 C40.2 R82.1 ; port V2-
V3+: C32.1 C41.1 R83.1 ; port V3+
V3-: C32.2 C42.2 R84.1 ; port V3-
NetJ11_1: J11.1 R123.1
NetJ11_2: J11.2 R120.1
NetJ12_1: J12.1 R125.1
NetJ12_2: J12.2 R128.1
NetJ13_1: J13.1 R127.1
NetJ13_2: J13.2 R130.1
NetR51_2: R51.2 R58.2 R59.2 T1.3
NetR75_2: R75.2 R85.2 R92.2 T2.3
NetR77_2: R77.2 R86.2 R93.2 T3.3
NetR79_2: R79.2 R87.1 R94.1 R112.2
NetR81_2: R81.2 R88.1 R95.1 R114.2
NetR83_2: R83.2 R89.1 R96.1 R116.2
NetR111_1: R111.1 R117.2
NetR111_2: R111.2 R112.1
NetR113_1: R113.1 R118.2
NetR113_2: R113.2 R114.1
NetR115_1: R115.1 R119.2
NetR115_2: R115.2 R116.1
NetR117_1: R117.1 R122.2
NetR118_1: R118.1 R124.2
NetR119_1: R119.1 R126.2
NetR121_1: R121.1 T1.1
NetR122_1: R122.1 R123.2
NetR124_1: R124.1 R125.2
NetR126_1: R126.1 R127.2
NetR129_1: R129.1 T2.1
NetR131_1: R131.1 T3.1

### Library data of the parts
C18 C24 C33-C42 = GRM21A5C2E470JW01D: CAP, CERM, 47pF, 500V, +/-5%, C0G/NP0, 0805; Manufacturer: MuRata; Polarized: N; CompType: Capacitor; U/M: EA; Cap_F: 0.000000000047; Tolerance_%: 5; Value1: Unknown; VDC_V: 250; Value2: 250V; TaMin_C: -55; TaMax_C: 125; Cap_Case: 0805
C21 C28-C32 = 08055C153KAT2A: CAP, CERM, 0.015uF, 50V, +/-10%, X7R, 0805; Manufacturer: AVX; Polarized: N; CompType: Capacitor; U/M: EA; Cap_F: 0.000000015; Tolerance_%: 10; ESR_Ohm: 0.063; Value1: 0.063 ohm; VDC_V: 50; TaMin_C: -55; TaMax_C: 125; Cap_Case: 0805
J11-J13 = ED120/2DS: TERMINAL BLOCK 5.08MM VERT 2POS, TH; Manufacturer: On-Shore Technology; SymbolCreator: a0412235; U/M: EA
R51 R66 R75-R84 = RC0603JR-071KL: RES, 1.0k ohm, 5%, 0.1W, 0603; Manufacturer: Vishay-Dale; CompType: Resistor; Res_ohm: 1000; Value_Code: 1k00; Tolerance_%: 5; Power_W: 0.1; VDC_V: 50; TempCo: 100 ppm/C; EIA_Code: E24; U/M: EA
R58 R59 R85 R86 R92 R93 = CRCW0603100RFKEA: RES, 100 ohm, 1%, 0.1W, 0603; Manufacturer: Vishay-Dale; CompType: Resistor; Value_Code: 100R; Tolerance_%: 1; Power_W: 0.1; VDC_V: 75; TempCo: 100 ppm/C; EIA_Code: E96; U/M: EA
R87-R89 R94-R96 = RC1206FR-072K4L: RES, 2.40 k, 1%, 0.25 W, 1206; Manufacturer: Yageo America; CompType: Resistor; Value: 2.40k; Res_ohm: 2400; Value_Code: 2k40; Tolerance_%: 1; Power_W: 0.25; Value2: 0.25W; VDC_V: 200; TempCo: 100 ppm/C; U/M: EA
R111-R119 R122 R124 R126 = ERJ-8ENF3323V: RES, 332 k, 1%, 0.25 W, 1206; Manufacturer: Panasonic; CompType: Resistor; Value: 332k; Res_ohm: 332000; Tolerance_%: 1; Power_W: 0.25; Value2: 0.25W; VDC_V: 200; TempCo: 100 ppm/C; EIA_Code: E96; U/M: EA
R120 R128 R130 = CRCW12060000Z0EA: RES, 0, 5%, 0.25 W, 1206; Manufacturer: Vishay-Dale; CompType: Resistor; Value: 0; Value_Code: 0000; Tolerance_%: 5; Power_W: 0.25; Value2: 0.25W; VDC_V: 200; TempCo: 200 ppm/C; EIA_Code: E24; U/M: EA
R121 R123 R125 R127 R129 R131 = CRCW0805330KJNEA: as R108 on sheet Pg3.MSP430F67791A+LED
T1-T3 = AP-2500: TRANSFORMER, PRECISE CURRENT, 15 A, 330 OHM, TH; Manufacturer: TALEMA GROUP LLC; SymbolCreator: x0199378

## Sheet Pg6.Isolated and Non Isolated Power Supply.SchDoc: Analog Front End Opamp (Voltage) + LDO + ZCD
size 431 x 279 mm; Date: Not shown in title block; ApprovedBy: Not shown in title block; CheckedBy: Not shown in title block; Author: Not shown in title block; CompanyName: Not shown in title block; Engineer: Not shown in title block; Organization: Not shown in title block; Address1: Not shown in title block; Address2: Not shown in title block; Address3: Not shown in title block; Address4: Not shown in title block; DocumentNumber: 4; Revision: Use project parameter SCH_Rev; SheetNumber: 6; SheetTotal: 10; PageSetup: Record=PageOptions¦CenterHorizontal=True¦CenterVertical=True¦PrintScale=1.00¦XCorrection=1.00¦YCorrection=1.00¦PrintKind=0¦BorderSize=5000000¦LeftOffset=0¦BottomOffset=0¦Orientation=2¦PaperLength=1000¦PaperWidth=1000¦Scale=100¦PaperSource=15¦PrintQuality=600¦MediaType=1¦DitherType=10¦PaperKind=Letter¦PrintScaleMode=1
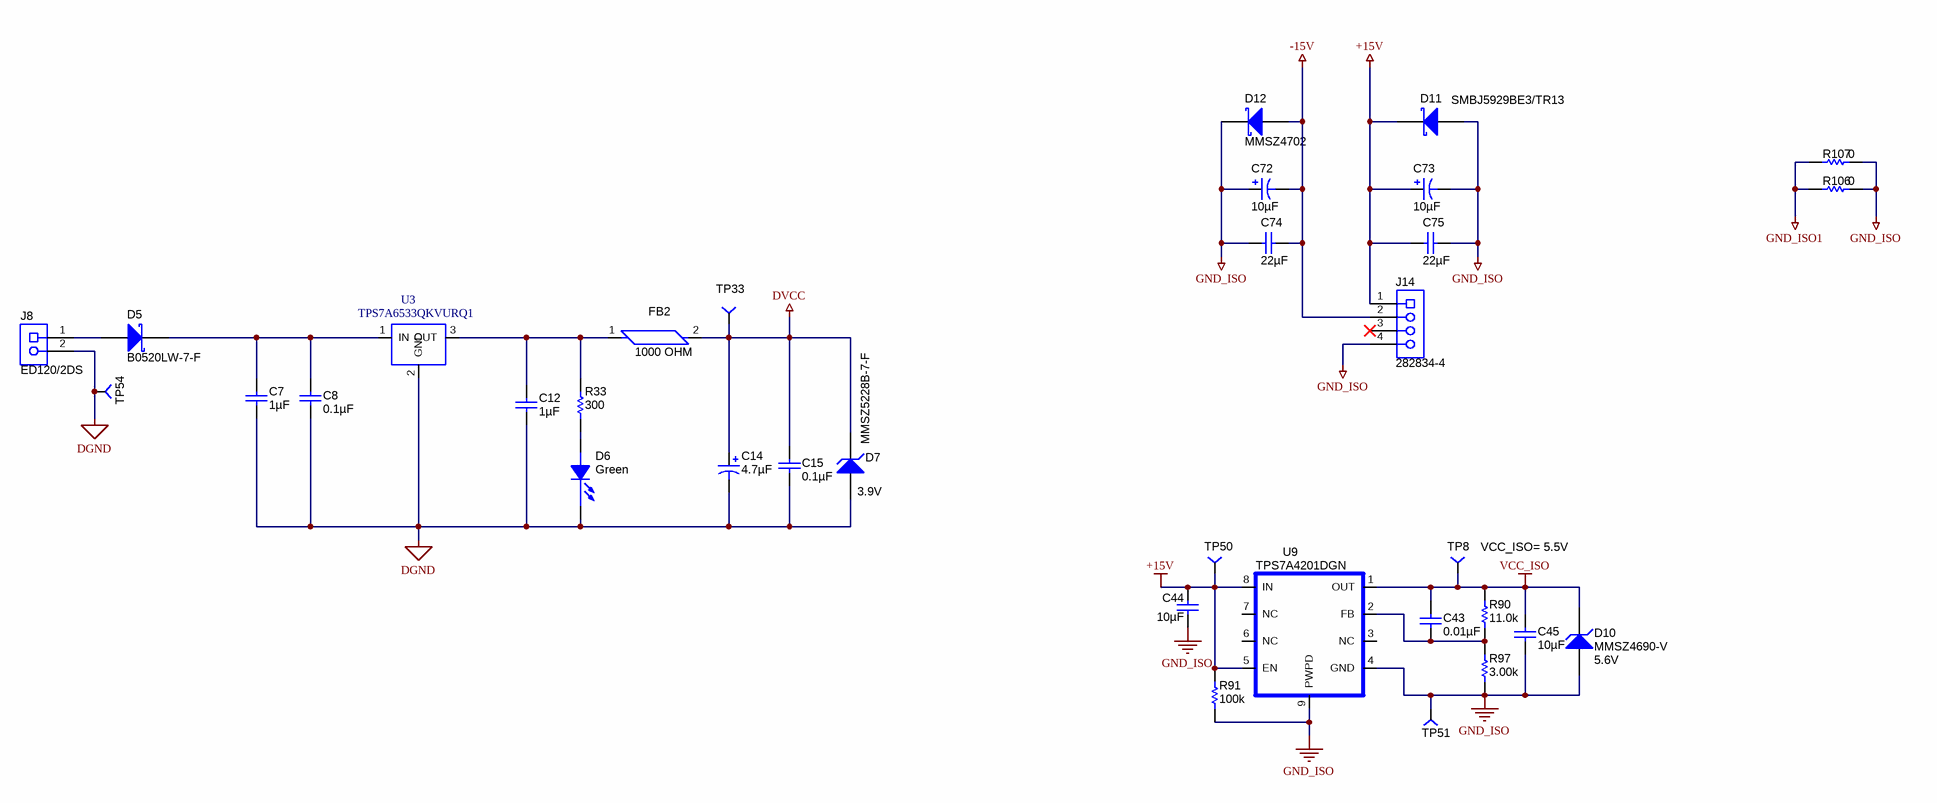
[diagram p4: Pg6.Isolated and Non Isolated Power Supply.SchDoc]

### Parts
C7  ValueDisplayed: 1µF  [0603]  (hidden comment: C1608X7R1C105K)
C8  ValueDisplayed: 0.1µF  [0603]  (hidden comment: C0603C104K5RACTU)
C12  ValueDisplayed: 1µF  [0603]  (hidden comment: C1608X7R1C105K)
C14  ValueDisplayed: 4.7µF  [6032-28]  (hidden comment: 293D475X9035C2TE3)
C15  ValueDisplayed: 0.1µF  [0603]  (hidden comment: C0603C104K5RACTU)
C43  ValueDisplayed: 0.01µF  [0603]  (hidden comment: C0603C103J5RACTU)
C44  ValueDisplayed: 10µF  [1210]  (hidden comment: GRM32ER71H106KA12L)
C45  ValueDisplayed: 10µF  [1206]  (hidden comment: GRM31CR71C106KAC7L)
C72  ValueDisplayed: 10µF  [6032-28]  (hidden comment: 293D106X9025C2TE3)
C73  ValueDisplayed: 10µF  [6032-28]  (hidden comment: TPSC106K025R0300)
C74  ValueDisplayed: 22µF  [0805_HV]  (hidden comment: GRM21BR61C226ME44)
C75  ValueDisplayed: 22µF  [0805_HV]  (hidden comment: GRM21BR61C226ME44)
D5  B0520LW-7-F  [DIO_SOD-123]
D6  value Green  [LED0603AA]  (hidden comment: LED_LG L29K-G2J1-24-Z)
D7  MMSZ5228B-7-F  value 3.9V  [sod-123]
D10  MMSZ4690-V  value 5.6V  [SOD-123]
D11  SMBJ5929BE3/TR13  [SMB]
D12  MMSZ4702  [SOD-123]
FB2  1000 OHM  [0603]
J8  ED120/2DS  [CONN_ED120-2DS]
J14  282834-4  [TEC_282834-4]
R33  value 300  [0603]  (hidden comment: CRCW0603300RJNEA)
R90  value 11.0k  [0603]  (hidden comment: CRCW060311K0FKEA)
R91  value 100k  [0603]  (hidden comment: CRCW0603100KFKEA)
R97  value 3.00k  [0603]  (hidden comment: RC0603FR-073KL)
R106  value 0  [1206]  (hidden comment: RC1206JR-070RL)
R107  value 0  [1206]  (hidden comment: RC1206JR-070RL)
TP8  TP-040_RND  [TP-040_RND]  (value not drawn)
TP33  TP-040_RND  [TP-040_RND]  (value not drawn)
TP50  TP-040_RND  [TP-040_RND]  (value not drawn)
TP51  TP-040_RND  [TP-040_RND]  (value not drawn)
TP54  TP-040_RND  [TP-040_RND]  (value not drawn)
U3  TPS7A6533QKVURQ1  [KVU_1]
U9  TPS7A4201DGN  [DGN_8P]

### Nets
+15V: C44.1 C73.1(+) C75.1 D11.1(K) J14.1 R91.2 TP50.1 U9.5(EN) U9.8(IN)
-15V: C72.2(-) C74.2 D12.2(A) J14.2
DGND: C7.2 C8.2 C12.2 C14.2(-) C15.2 D6.1(C) D7.2(A) J8.2 TP54.1 U3.2(GND)
DVCC: C14.1(+) C15.1 D7.1(K) FB2.2 TP33.1
GND_ISO: C44.2 C45.1 C72.1(+) C73.2(-) C74.1 C75.2 D10.2(A) D11.2(A) D12.1(K) J14.4 R91.1 R97.2 R106.2 R107.2 TP51.1 U9.4(GND) U9.9(PWPD)
GND_ISO1: R106.1 R107.1
VCC_ISO: C43.2 C45.2 D10.1(K) R90.2 TP8.1 U9.1(OUT)
NetC7_1: C7.1 C8.1 D5.1(K) U3.1(IN)
NetC12_1: C12.1 FB2.1 R33.2 U3.3(OUT)
NetC43_1: C43.1 R90.1 R97.1 U9.2(FB)
NetD5_2: D5.2(A) J8.1
NetD6_2: D6.2(A) R33.1

Not connected (* = marked no-connect by the designer): J14 3*; U9 3(NC) 6(NC) 7(NC)

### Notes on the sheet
- VCC_ISO= 5.5V

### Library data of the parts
C7 C12 = C1608X7R1C105K: CAP, CERM, 1uF, 16V, +/-10%, X7R, 0603; Manufacturer: TDK; Polarized: N; CompType: Capacitor; U/M: EA; Cap_F: 0.000001; Tolerance_%: 10; ESR_Ohm: 0.0057; Value1: 0.0057 ohm; VDC_V: 16; TaMin_C: -55; TaMax_C: 125
C8 C15 = C0603C104K5RACTU: CAP, CERM, 0.1uF, 50V, +/-10%, X7R, 0603; Manufacturer: Kemet; Polarized: N; CompType: Capacitor; U/M: EA; Cap_F: 0.0000001; Tolerance_%: 10; Value1: Unknown; VDC_V: 50; TaMin_C: -55; TaMax_C: 125
C14 = 293D475X9035C2TE3: CAP, TA, 4.7uF, 35V, +/-10%, 1.9 ohm, SMD; Manufacturer: Vishay-Sprague; Polarized: Y; CompType: Capacitor; U/M: EA; Cap_F: 0.0000047; Tolerance_%: 10; Value1: 1.9 ohm; VDC_V: 35; ESR_Ohm: 1.9; IRMS_A: 0.24; TaMin_C: -55; TaMax_C: 125; Cap_Case: C
C43 = C0603C103J5RACTU: CAP, CERM, 0.01uF, 50V, +/-5%, X7R, 0603; Manufacturer: Kemet; Polarized: N; CompType: Capacitor; U/M: EA; Cap_F: 0.00000001; Tolerance_%: 5; Value1: Unknown; VDC_V: 50; TaMin_C: -55; TaMax_C: 125
C44 = GRM32ER71H106KA12L: as C46 on sheet Pg4. Relay Drivers+JTAG Interface +Decoupling Capacitors
C45 = GRM31CR71C106KAC7L: CAP, CERM, 10uF, 16V, +/-10%, X7R, 1206; Manufacturer: MuRata; Polarized: N; CompType: Capacitor; U/M: EA; Cap_F: 0.00001; Tolerance_%: 10; Value1: Unknown; VDC_V: 16; TaMin_C: -55; TaMax_C: 125
C72 = 293D106X9025C2TE3: CAP, TA, 10uF, 25V, +/-10%, 1.5 ohm, SMD; Manufacturer: Vishay-Sprague; Polarized: Y; CompType: Capacitor; U/M: EA; Cap_F: 0.00001; Tolerance_%: 10; Value1: 1.5 ohm; VDC_V: 25; ESR_Ohm: 1.5; IRMS_A: 0.27; TaMin_C: -55; TaMax_C: 125; Cap_Case: C
C73 = TPSC106K025R0300: CAP, TA, 10uF, 25V, +/-10%, 0.3 ohm, SMD; Manufacturer: AVX; Polarized: Y; CompType: Capacitor; U/M: EA; Cap_F: 0.00001; Tolerance_%: 10; Value1: 0.3 ohm; VDC_V: 25; ESR_Ohm: 0.3; IRMS_A: 0.545; TaMin_C: -55; TaMax_C: 125; Cap_Case: C
C74 C75 = GRM21BR61C226ME44: CAP, CERM, 22uF, 16V, +/-20%, X5R, 0805; Manufacturer: MuRata; Polarized: N; CompType: Capacitor; U/M: EA; Cap_F: 0.000022; Tolerance_%: 20; Value1: Unknown; VDC_V: 16; TaMin_C: -55; TaMax_C: 85; Cap_Case: 0805
D5 = B0520LW-7-F: DIODE, SCHOTTKY, 20V, 500 mA, SOD123, SMT; Manufacturer: DIODE INCORPORATED; SymbolCreator: x0199378
D6 = LED_LG L29K-G2J1-24-Z: LED SmartLED Green 570NM; Manufacturer: OSRAM; SymbolCreator: x0120606
D7 = 1SMB5915BT3G: DIODE ZENER 3.9V 500MW SOD123; Manufacturer: Diodes Incorporated; U/M: EA; Power_W: 0.55; Vz_V: 3.9; Value1: 0.55W; RJA_CperW: 226
D10 = MMSZ4690-V: Diode, Zener, 5.6 V, 500 mW, SOD-123; Manufacturer: Vishay-Semiconductor; SymbolCreator: a0412235; U/M: EA; Power_W: 0.5; Vz_V: 5.6; Value1: 0.5W; RJA_CperW: 67; AEC Category: AEC-Q101
D11 = SL43-E3/57T: DIODE ZENER 15V 2W D0214AA; Manufacturer: Microsemi Commercial Component  Group; U/M: EA; Io_A: 4; RJC_CperW: 14
D12 = SL43-E3/57T: DIODE ZENER 15V 500MW SOD123; Manufacturer: Fairchild semiconductor; U/M: EA; Io_A: 4; TJmax_C: 125; RJC_CperW: 14
FB2 = MMZ1608B102C: as FB4 on sheet Pg4. Relay Drivers+JTAG Interface +Decoupling Capacitors
J8 = ED120/2DS: as J11 on sheet Pg5.Analog Front End - Current and Voltage
J14 = 282834-4: Receptacle, 100mil, 4X1 TH; Manufacturer: TE Connectivity; SymbolCreator: a0411947; U/M: EA
R33 = CRCW0603300RJNEA: as R18 on sheet Pg3.MSP430F67791A+LED
R90 = CRCW060311K0FKEA: RES, 11.0k ohm, 1%, 0.1W, 0603; Manufacturer: Vishay-Dale; CompType: Resistor; Res_ohm: 11000; Value_Code: 11k0; Tolerance_%: 1; Power_W: 0.1; VDC_V: 75; TempCo: 100 ppm/C; EIA_Code: E96; U/M: EA
R91 = CRCW0603100KFKEA: RES, 100k ohm, 1%, 0.1W, 0603; Manufacturer: Vishay-Dale; CompType: Resistor; Res_ohm: 100000; Tolerance_%: 1; Power_W: 0.1; VDC_V: 75; TempCo: 100 ppm/C; EIA_Code: E96; U/M: EA
R97 = RC0603FR-073KL: RES, 3.00k ohm, 1%, 0.1W, 0603; Manufacturer: Yageo America; CompType: Resistor; Res_ohm: 3000; Value_Code: 3k00; Tolerance_%: 1; Power_W: 0.1; VDC_V: 150; TempCo: 200 ppm/C; U/M: EA
R106 R107 = RC0402JR-070RL: RES, 0 ohm,5%, 0.25W, 1206; Manufacturer: Yageo America; CompType: Resistor; Value_Code: 0000; Tolerance_%: 5; Power_W: 0.1; Value2: 0.125W; VDC_V: 50; TempCo: 200 ppm/C; EIA_Code: E24; U/M: EA
TP8 TP33 TP50 TP51 TP54 = TP-040_RND: as TP31 on sheet Pg3.MSP430F67791A+LED
U3 = TPS7A6533QKVURQ1: IC, 300-mA 40-V LOW-DROPOUT REGULATOR WITH 25-uA QUIESCENT CURRENT; Manufacturer: TI; Alternate Manufacturer: None; Area: 136210
U9 = TPS7A4201DGN: IC, 28-V Input Voltage, 50-mA Voltage Regulator; Manufacturer: TI; Alternate Manufacturer: None; Area: 22.68 mm

## Sheet Pg7.Digital Isolators.SchDoc
size 431 x 279 mm; Date: Not shown in title block; ApprovedBy: Not shown in title block; CheckedBy: Not shown in title block; Author: Not shown in title block; CompanyName: Not shown in title block; Engineer: Not shown in title block; Organization: Not shown in title block; Address1: Not shown in title block; Address2: Not shown in title block; Address3: Not shown in title block; Address4: Not shown in title block; DocumentNumber: 7; Revision: Use project parameter SCH_Rev; SheetNumber: 7; SheetTotal: 10; PageSetup: Record=PageOptions¦CenterHorizontal=True¦CenterVertical=True¦PrintScale=1.00¦XCorrection=1.00¦YCorrection=1.00¦PrintKind=0¦BorderSize=5000000¦LeftOffset=0¦BottomOffset=0¦Orientation=2¦PaperLength=1000¦PaperWidth=1000¦Scale=100¦PaperSource=15¦PrintQuality=600¦MediaType=1¦DitherType=10¦PaperKind=Letter¦PrintScaleMode=1
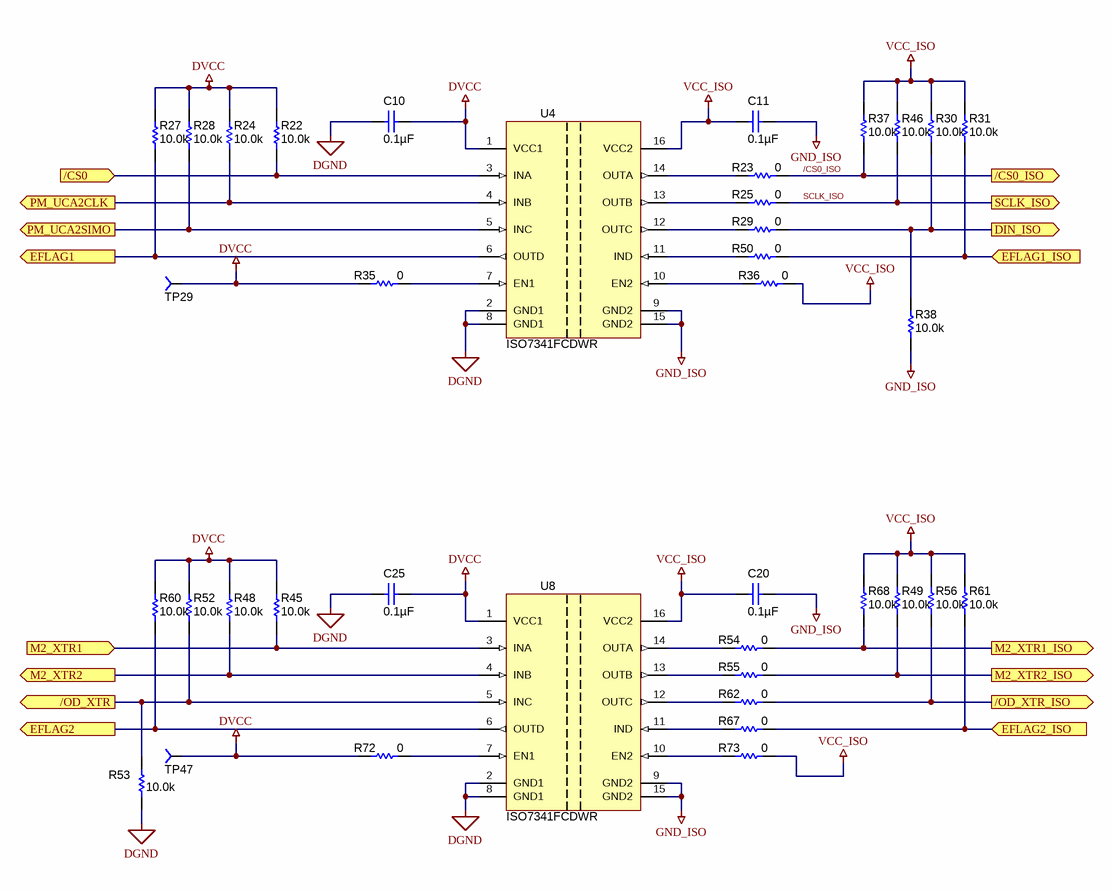
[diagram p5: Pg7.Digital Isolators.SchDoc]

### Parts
C10  ValueDisplayed: 0.1µF  [0603]  (hidden comment: C0603C104K5RACTU)
C11  ValueDisplayed: 0.1µF  [0603]  (hidden comment: C0603C104K5RACTU)
C20  ValueDisplayed: 0.1µF  [0603]  (hidden comment: C0603C104K5RACTU)
C25  ValueDisplayed: 0.1µF  [0603]  (hidden comment: C0603C104K5RACTU)
R22  value 10.0k  [0603]  (hidden comment: CRCW060310K0FKEA)
R23  value 0  [0603]  (hidden comment: RC0603JR-070RL)
R24  value 10.0k  [0603]  (hidden comment: CRCW060310K0FKEA)
R25  value 0  [0603]  (hidden comment: RC0603JR-070RL)
R27  value 10.0k  [0603]  (hidden comment: CRCW060310K0FKEA)
R28  value 10.0k  [0603]  (hidden comment: CRCW060310K0FKEA)
R29  value 0  [0603]  (hidden comment: RC0603JR-070RL)
R30  value 10.0k  [0603]  (hidden comment: CRCW060310K0FKEA)
R31  value 10.0k  [0603]  (hidden comment: CRCW060310K0FKEA)
R35  value 0  [0603]  (hidden comment: RC0603JR-070RL)
R36  value 0  [0603]  (hidden comment: RC0603JR-070RL)
R37  value 10.0k  [0603]  (hidden comment: CRCW060310K0FKEA)
R38  value 10.0k  [0603]  (hidden comment: CRCW060310K0FKEA)
R45  value 10.0k  [0603]  (hidden comment: CRCW060310K0FKEA)
R46  value 10.0k  [0603]  (hidden comment: CRCW060310K0FKEA)
R48  value 10.0k  [0603]  (hidden comment: CRCW060310K0FKEA)
R49  value 10.0k  [0603]  (hidden comment: CRCW060310K0FKEA)
R50  value 0  [0603]  (hidden comment: RC0603JR-070RL)
R52  value 10.0k  [0603]  (hidden comment: CRCW060310K0FKEA)
R53  value 10.0k  [0603]  (hidden comment: CRCW060310K0FKEA)
R54  value 0  [0603]  (hidden comment: RC0603JR-070RL)
R55  value 0  [0603]  (hidden comment: RC0603JR-070RL)
R56  value 10.0k  [0603]  (hidden comment: CRCW060310K0FKEA)
R60  value 10.0k  [0603]  (hidden comment: CRCW060310K0FKEA)
R61  value 10.0k  [0603]  (hidden comment: CRCW060310K0FKEA)
R62  value 0  [0603]  (hidden comment: RC0603JR-070RL)
R67  value 0  [0603]  (hidden comment: RC0603JR-070RL)
R68  value 10.0k  [0603]  (hidden comment: CRCW060310K0FKEA)
R72  value 0  [0603]  (hidden comment: RC0603JR-070RL)
R73  value 0  [0603]  (hidden comment: RC0603JR-070RL)
TP29  TP1_PD40_D0.5_S50  [TP1_PD40_D0.5_S50]  (value not drawn)
TP47  TP1_PD40_D0.5_S50  [TP1_PD40_D0.5_S50]  (value not drawn)
U4  ISO7341FCDWR  [DW0016B_N]
U8  ISO7341FCDWR  [DW0016B_N]

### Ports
/CS0 (in), /CS0_ISO (out), /OD_XTR (out), /OD_XTR_ISO (out), DIN_ISO (out), EFLAG1 (out), EFLAG1_ISO (in), EFLAG2 (out), EFLAG2_ISO (in), M2_XTR1 (in), M2_XTR1_ISO (out), M2_XTR2 (out), M2_XTR2_ISO (out), PM_UCA2CLK (out), PM_UCA2SIMO (out), SCLK_ISO (out)

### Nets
DGND: C10.1 C25.1 R53.1 U4.2(GND1) U4.8(GND1) U8.2(GND1) U8.8(GND1)
DVCC: C10.2 C25.2 R22.2 R24.2 R27.2 R28.2 R35.1 R45.2 R48.2 R52.2 R60.2 R72.1 TP29.1 TP47.1 U4.1(VCC1) U8.1(VCC1)
GND_ISO: C11.2 C20.2 R38.1 U4.9(GND2) U4.15(GND2) U8.9(GND2) U8.15(GND2)
VCC_ISO: C11.1 C20.1 R30.2 R31.2 R36.2 R37.2 R46.2 R49.2 R56.2 R61.2 R68.2 R73.2 U4.16(VCC2) U8.16(VCC2)
/CS0: R22.1 U4.3(INA) ; port /CS0
/CS0_ISO: R23.2 R37.1 ; port /CS0_ISO
/OD_XTR: R52.1 R53.2 U8.5(INC) ; port /OD_XTR
/OD_XTR_ISO: R56.1 R62.2 ; port /OD_XTR_ISO
DIN_ISO: R29.2 R30.1 R38.2 ; port DIN_ISO
EFLAG1: R27.1 U4.6(OUTD) ; port EFLAG1
EFLAG1_ISO: R31.1 R50.2 ; port EFLAG1_ISO
EFLAG2: R60.1 U8.6(OUTD) ; port EFLAG2
EFLAG2_ISO: R61.1 R67.2 ; port EFLAG2_ISO
M2_XTR1: R45.1 U8.3(INA) ; port M2_XTR1
M2_XTR1_ISO: R54.2 R68.1 ; port M2_XTR1_ISO
M2_XTR2: R48.1 U8.4(INB) ; port M2_XTR2
M2_XTR2_ISO: R49.1 R55.2 ; port M2_XTR2_ISO
PM_UCA2CLK: R24.1 U4.4(INB) ; port PM_UCA2CLK
PM_UCA2SIMO: R28.1 U4.5(INC) ; port PM_UCA2SIMO
SCLK_ISO: R25.2 R46.1 ; port SCLK_ISO
NetR23_1: R23.1 U4.14(OUTA)
NetR25_1: R25.1 U4.13(OUTB)
NetR29_1: R29.1 U4.12(OUTC)
NetR35_2: R35.2 U4.7(EN1)
NetR36_1: R36.1 U4.10(EN2)
NetR50_1: R50.1 U4.11(IND)
NetR54_1: R54.1 U8.14(OUTA)
NetR55_1: R55.1 U8.13(OUTB)
NetR62_1: R62.1 U8.12(OUTC)
NetR67_1: R67.1 U8.11(IND)
NetR72_2: R72.2 U8.7(EN1)
NetR73_1: R73.1 U8.10(EN2)

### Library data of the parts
C10 C11 C20 C25 = C0603C104K5RACTU: as C8 on sheet Pg6.Isolated and Non Isolated Power Supply
R22 R24 R27 R28 R30 R31 R37 R38 R45 R46 R48 R49 R52 R53 R56 R60 R61 R68 = RG1608P-103-B-T5: RES, 10.0k ohm, 1%, 0.1W, 0603; Manufacturer: Vishay Dale; CompType: Resistor; Res_ohm: 10000; Value_Code: 10k0; Tolerance_%: 1; Power_W: 0.1; VDC_V: 75; TempCo: 25 ppm/C; EIA_Code: E192; U/M: EA
R23 R25 R29 R35 R36 R50 R54 R55 R62 R67 R72 R73 = RC0402JR-070RL: RES, 0 ohm,5%, 0.1W, 0603; Manufacturer: Yageo America; CompType: Resistor; Value_Code: 0000; Tolerance_%: 5; Power_W: 0.1; VDC_V: 50; TempCo: 200 ppm/C; EIA_Code: E24; U/M: EA
TP29 TP47 = TP-040_RND: Test Point 40mil pad 20mil drill; Manufacturer: STD; Value: STD
U4 U8 = ISO7341FCDWR: Robust EMC, Low Power, Quad-Channel Digital Isolators, DW0016B; Manufacturer: Texas Instruments; SymbolCreator: Altium; CompType: IC; U/M: EA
